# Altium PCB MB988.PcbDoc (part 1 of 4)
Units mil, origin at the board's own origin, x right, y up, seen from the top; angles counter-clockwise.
Board outline 4505 x 6805 mil, 4 copper layers (TopLayer, VCC, GND, BottomLayer), stack 71.6 mil thick; 546 components, 390 nets, 1907 pads, 809 vias.
Unrouted connection lines stored in the file: 2.
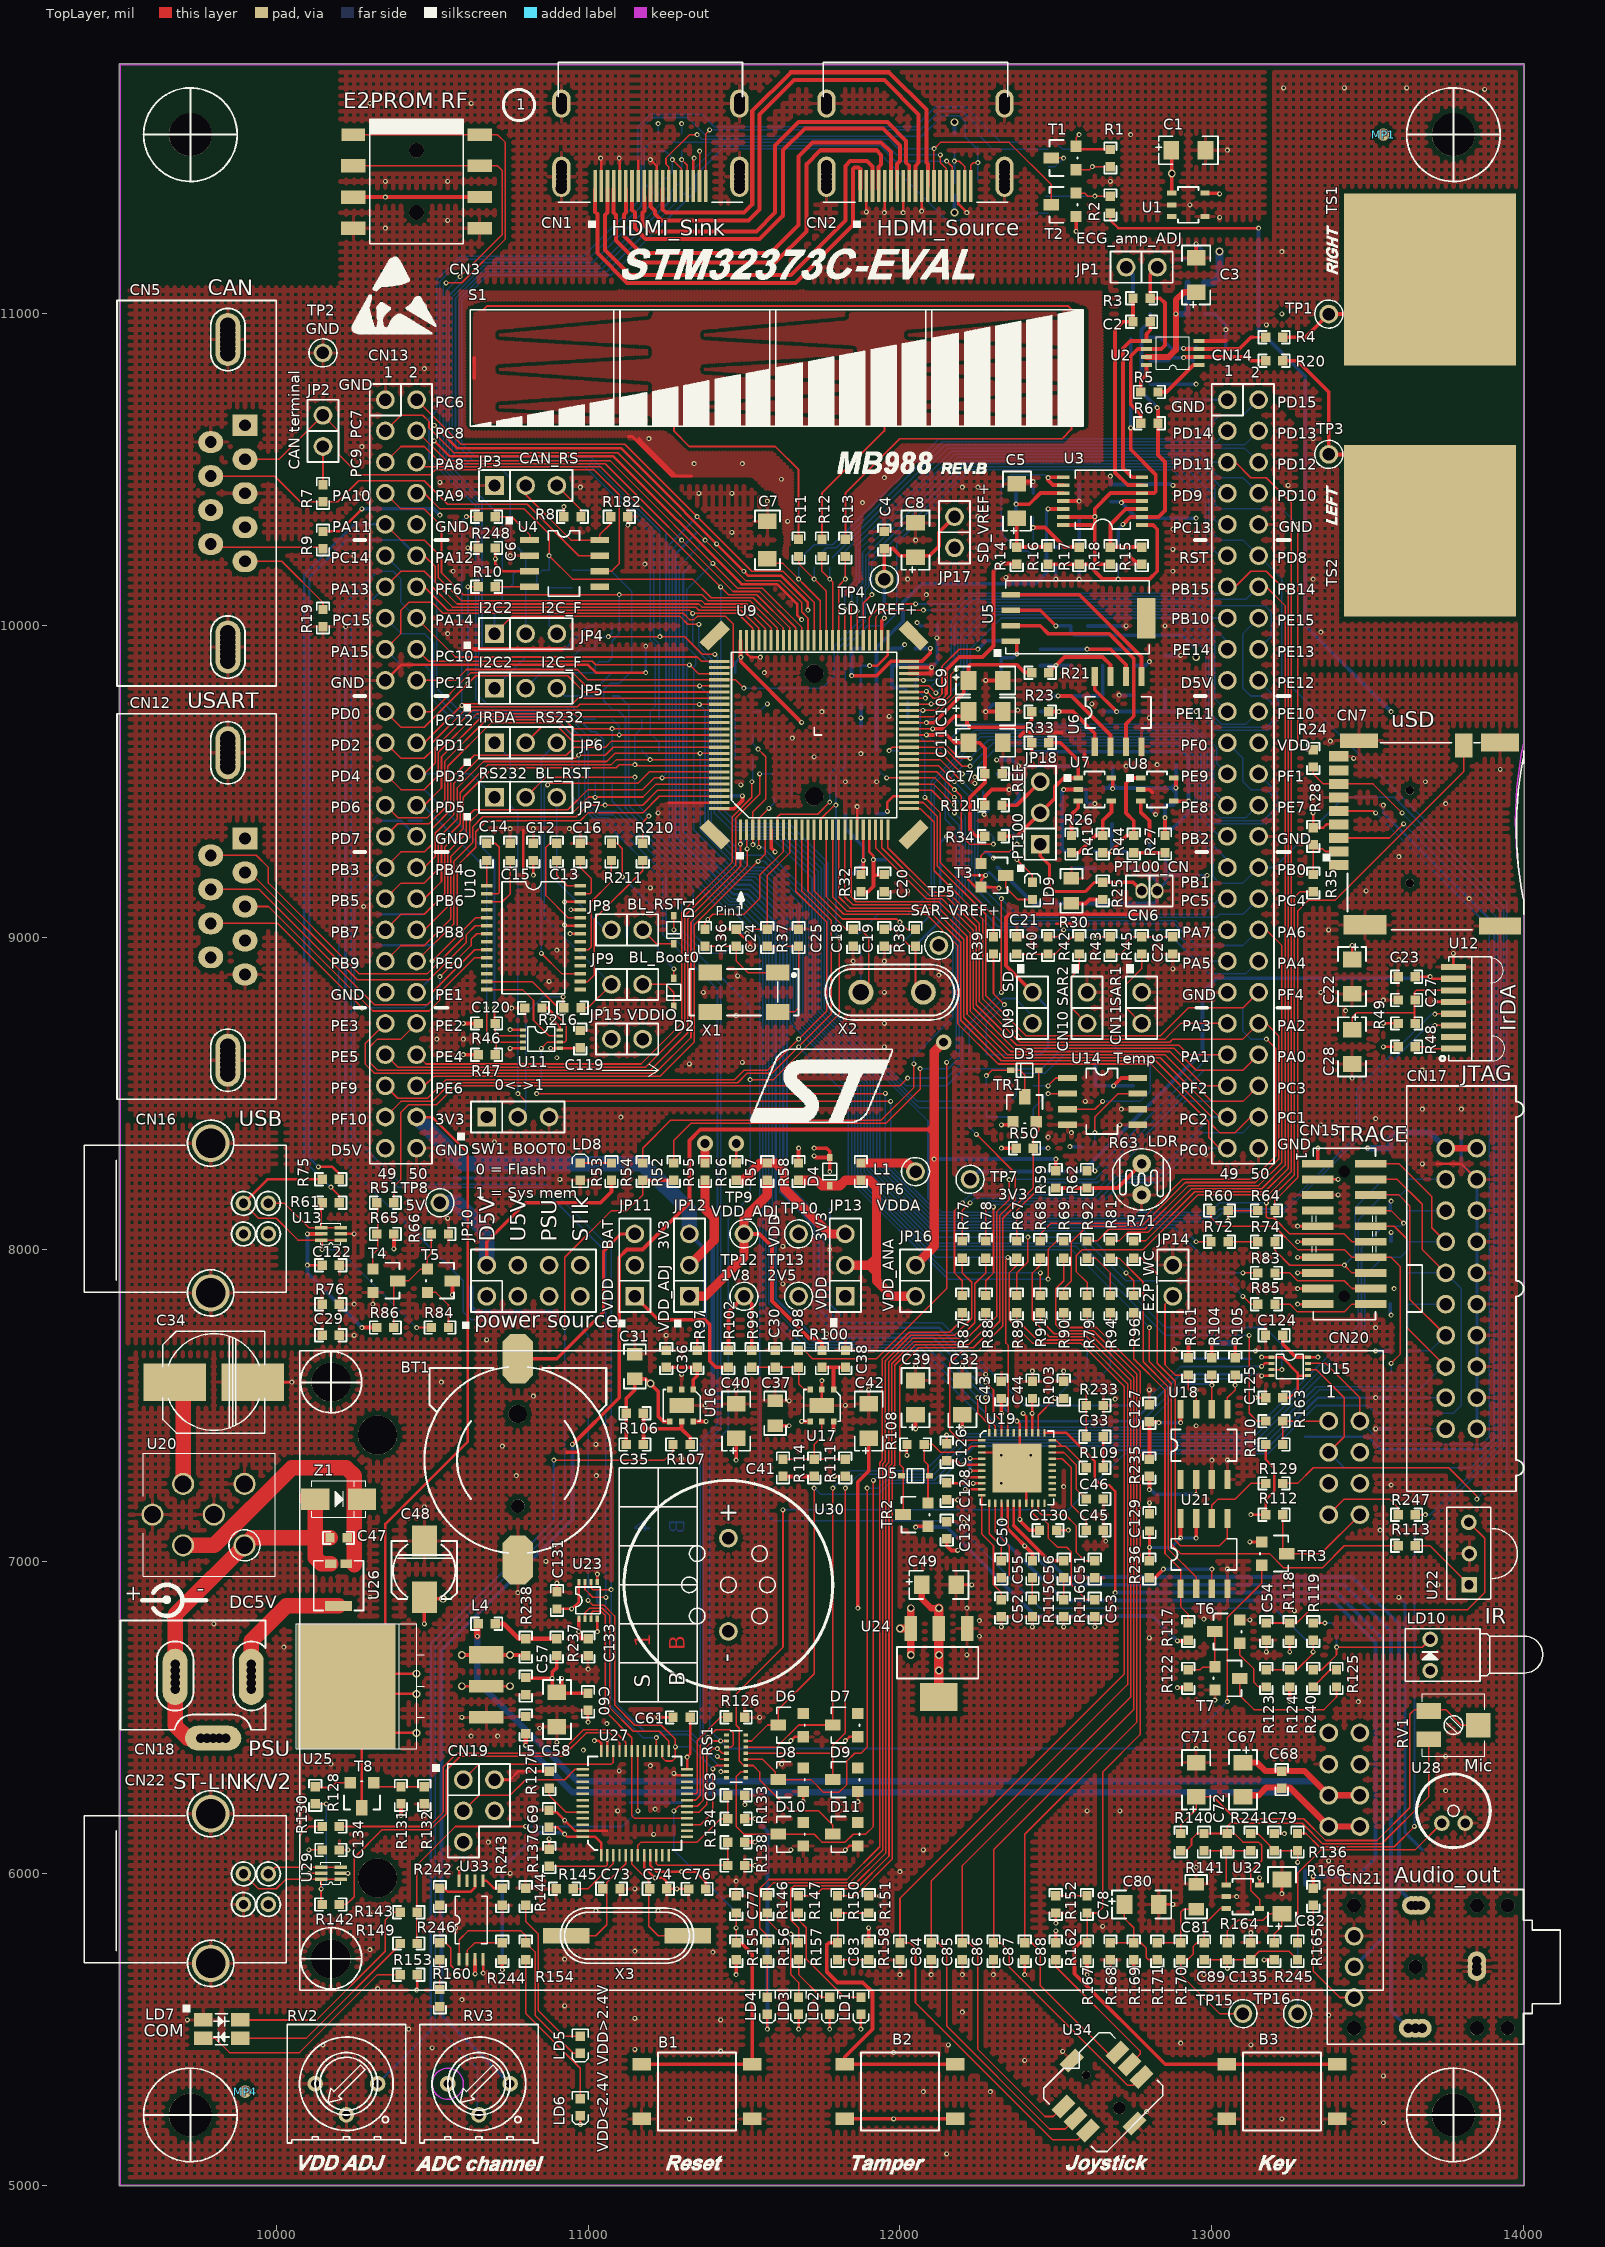
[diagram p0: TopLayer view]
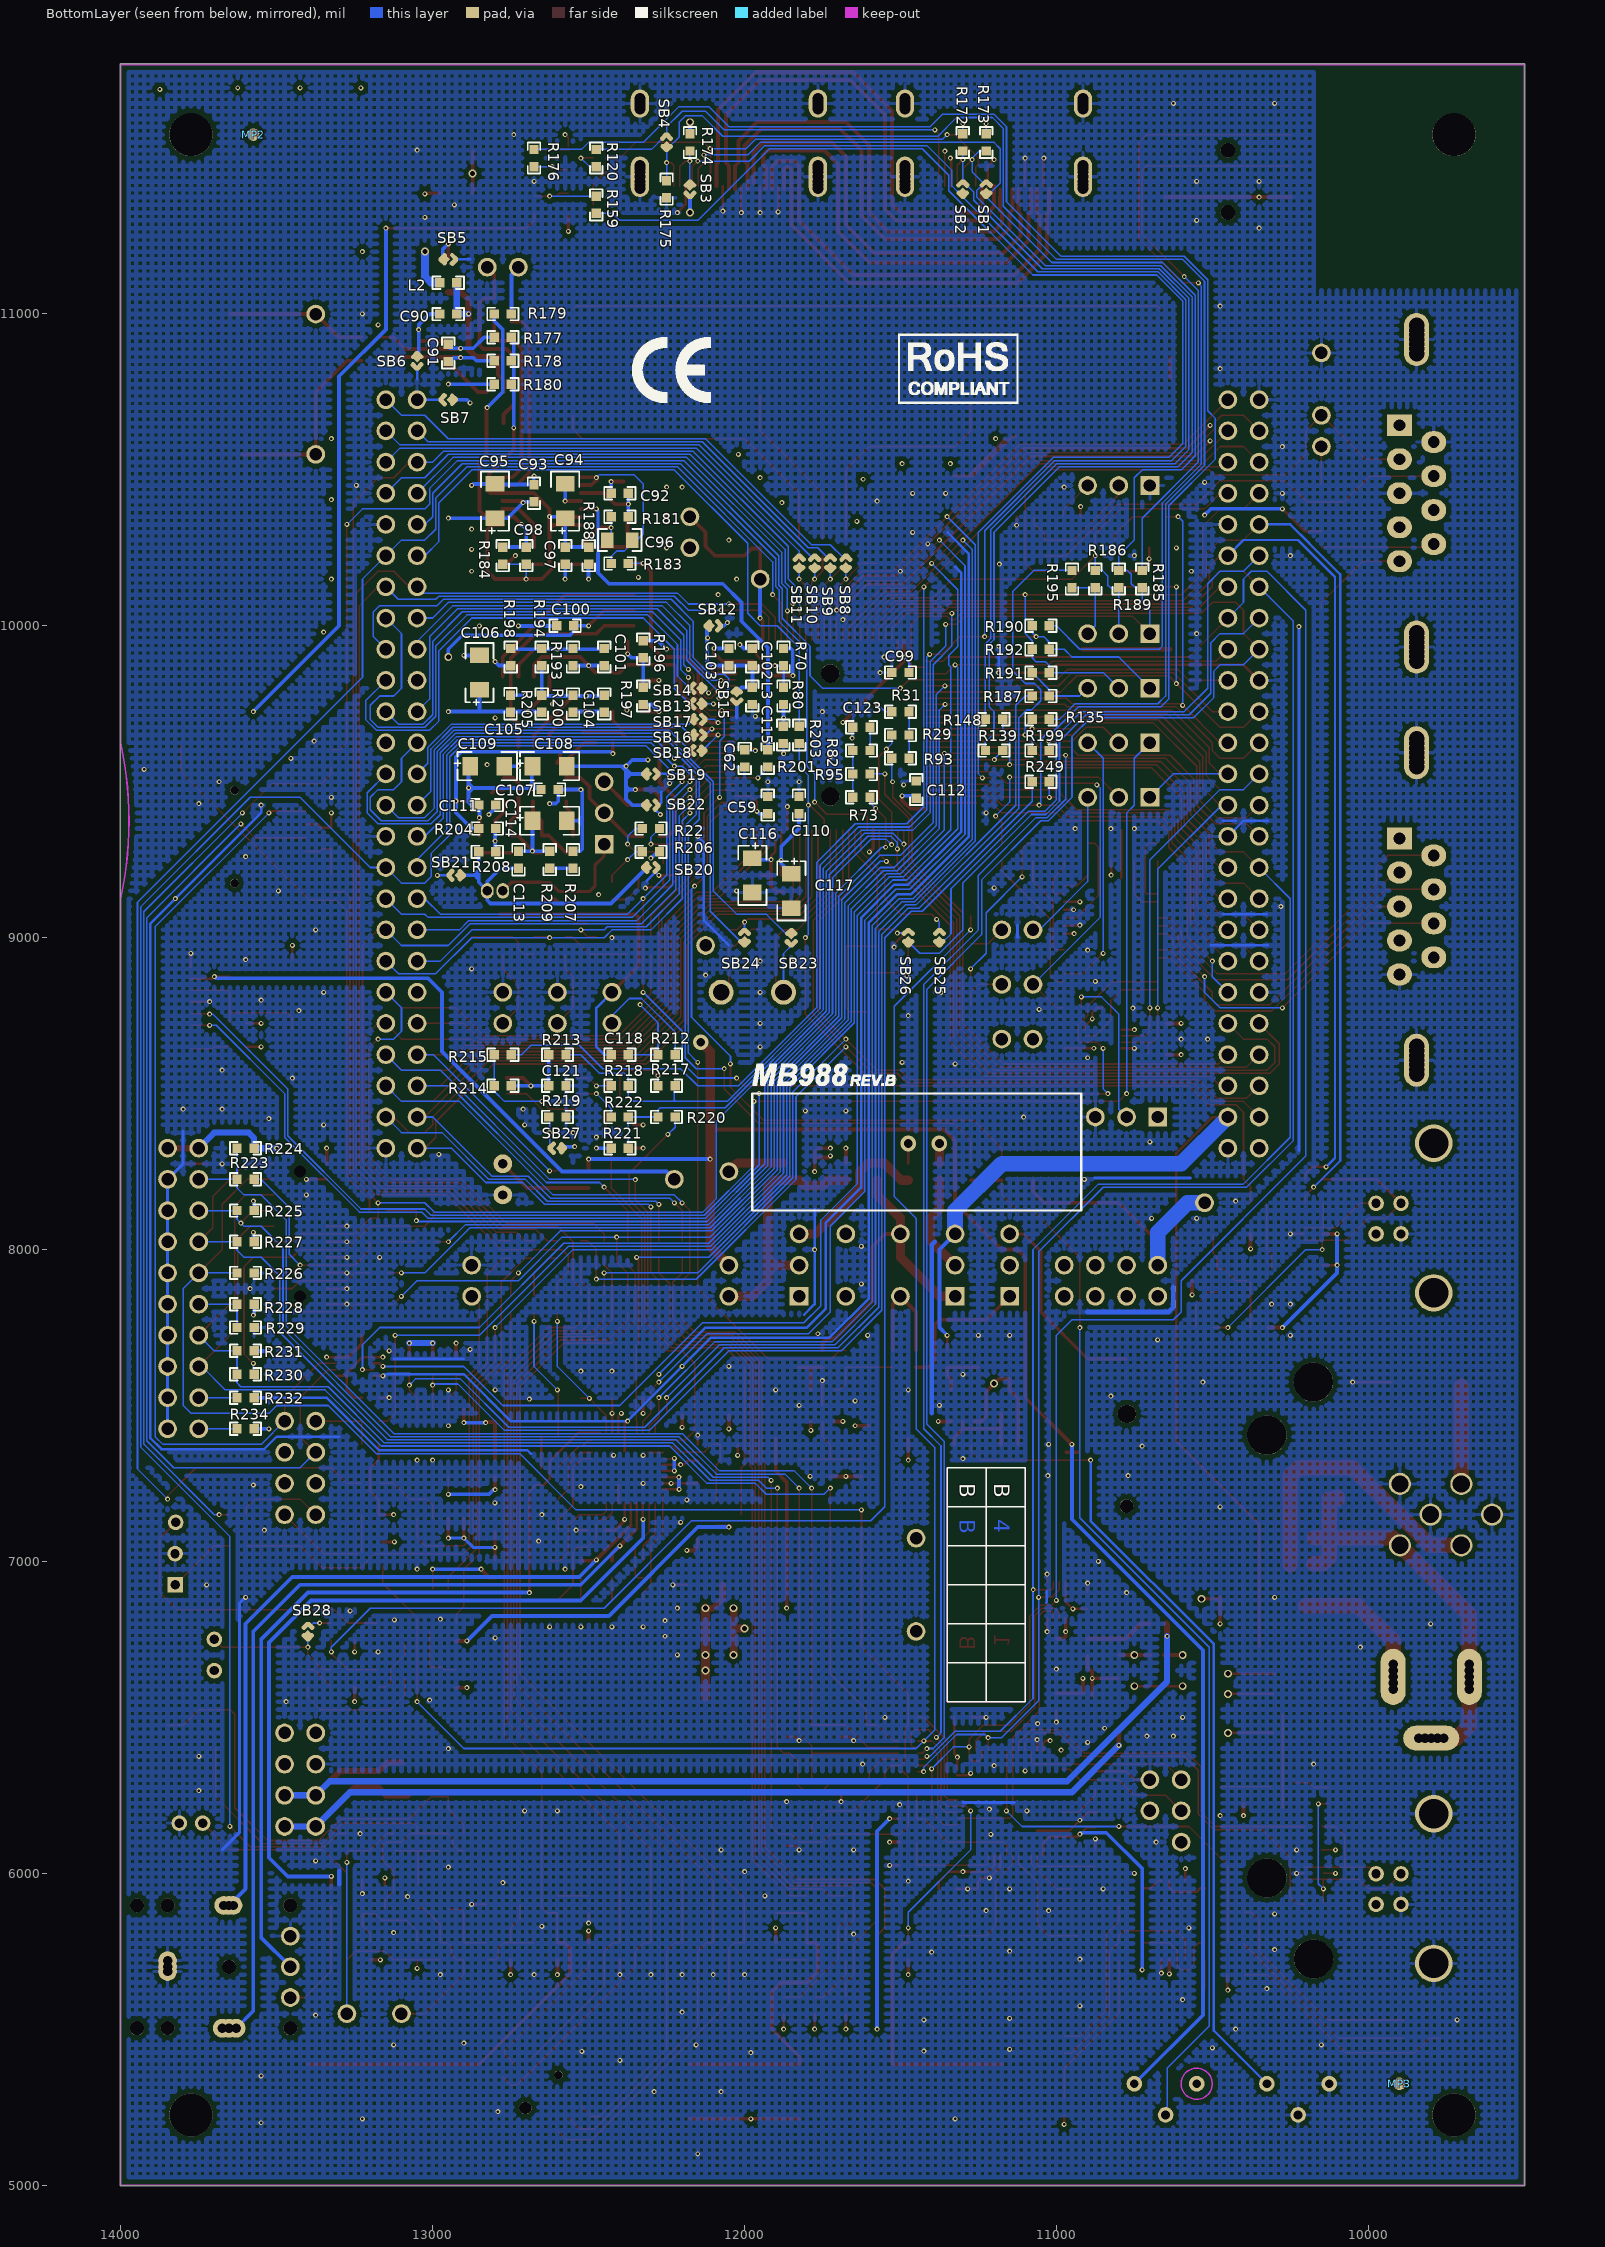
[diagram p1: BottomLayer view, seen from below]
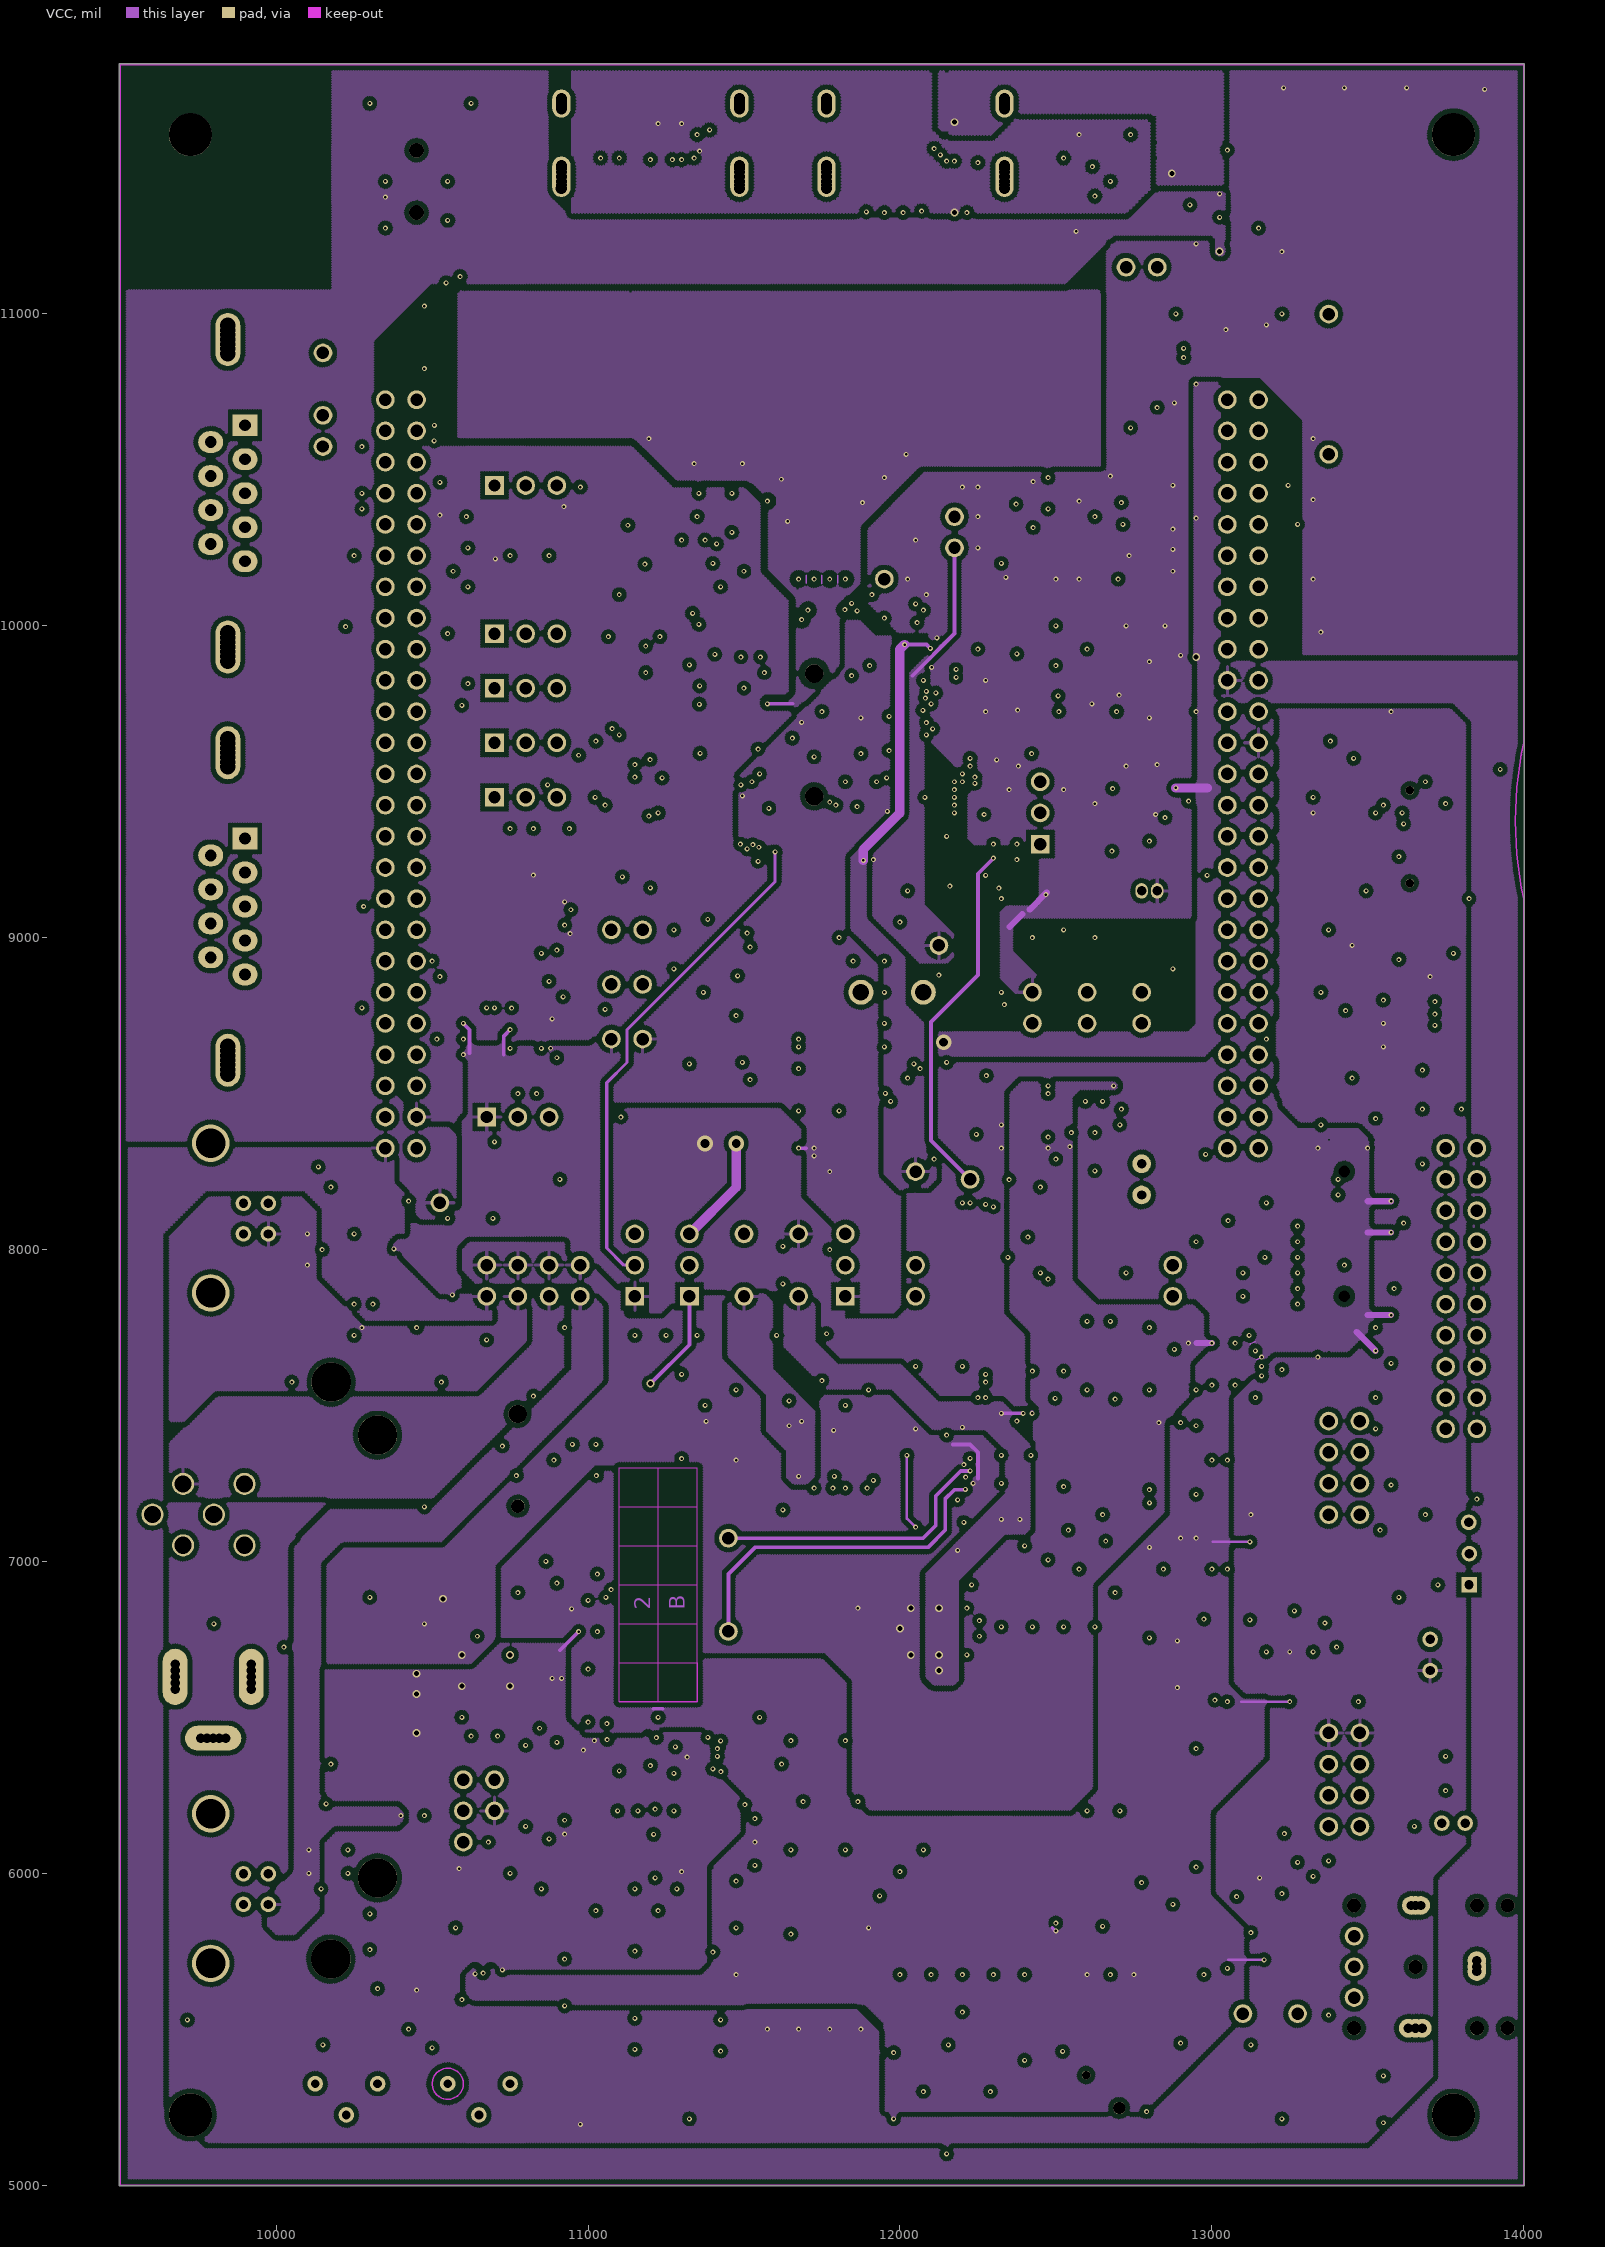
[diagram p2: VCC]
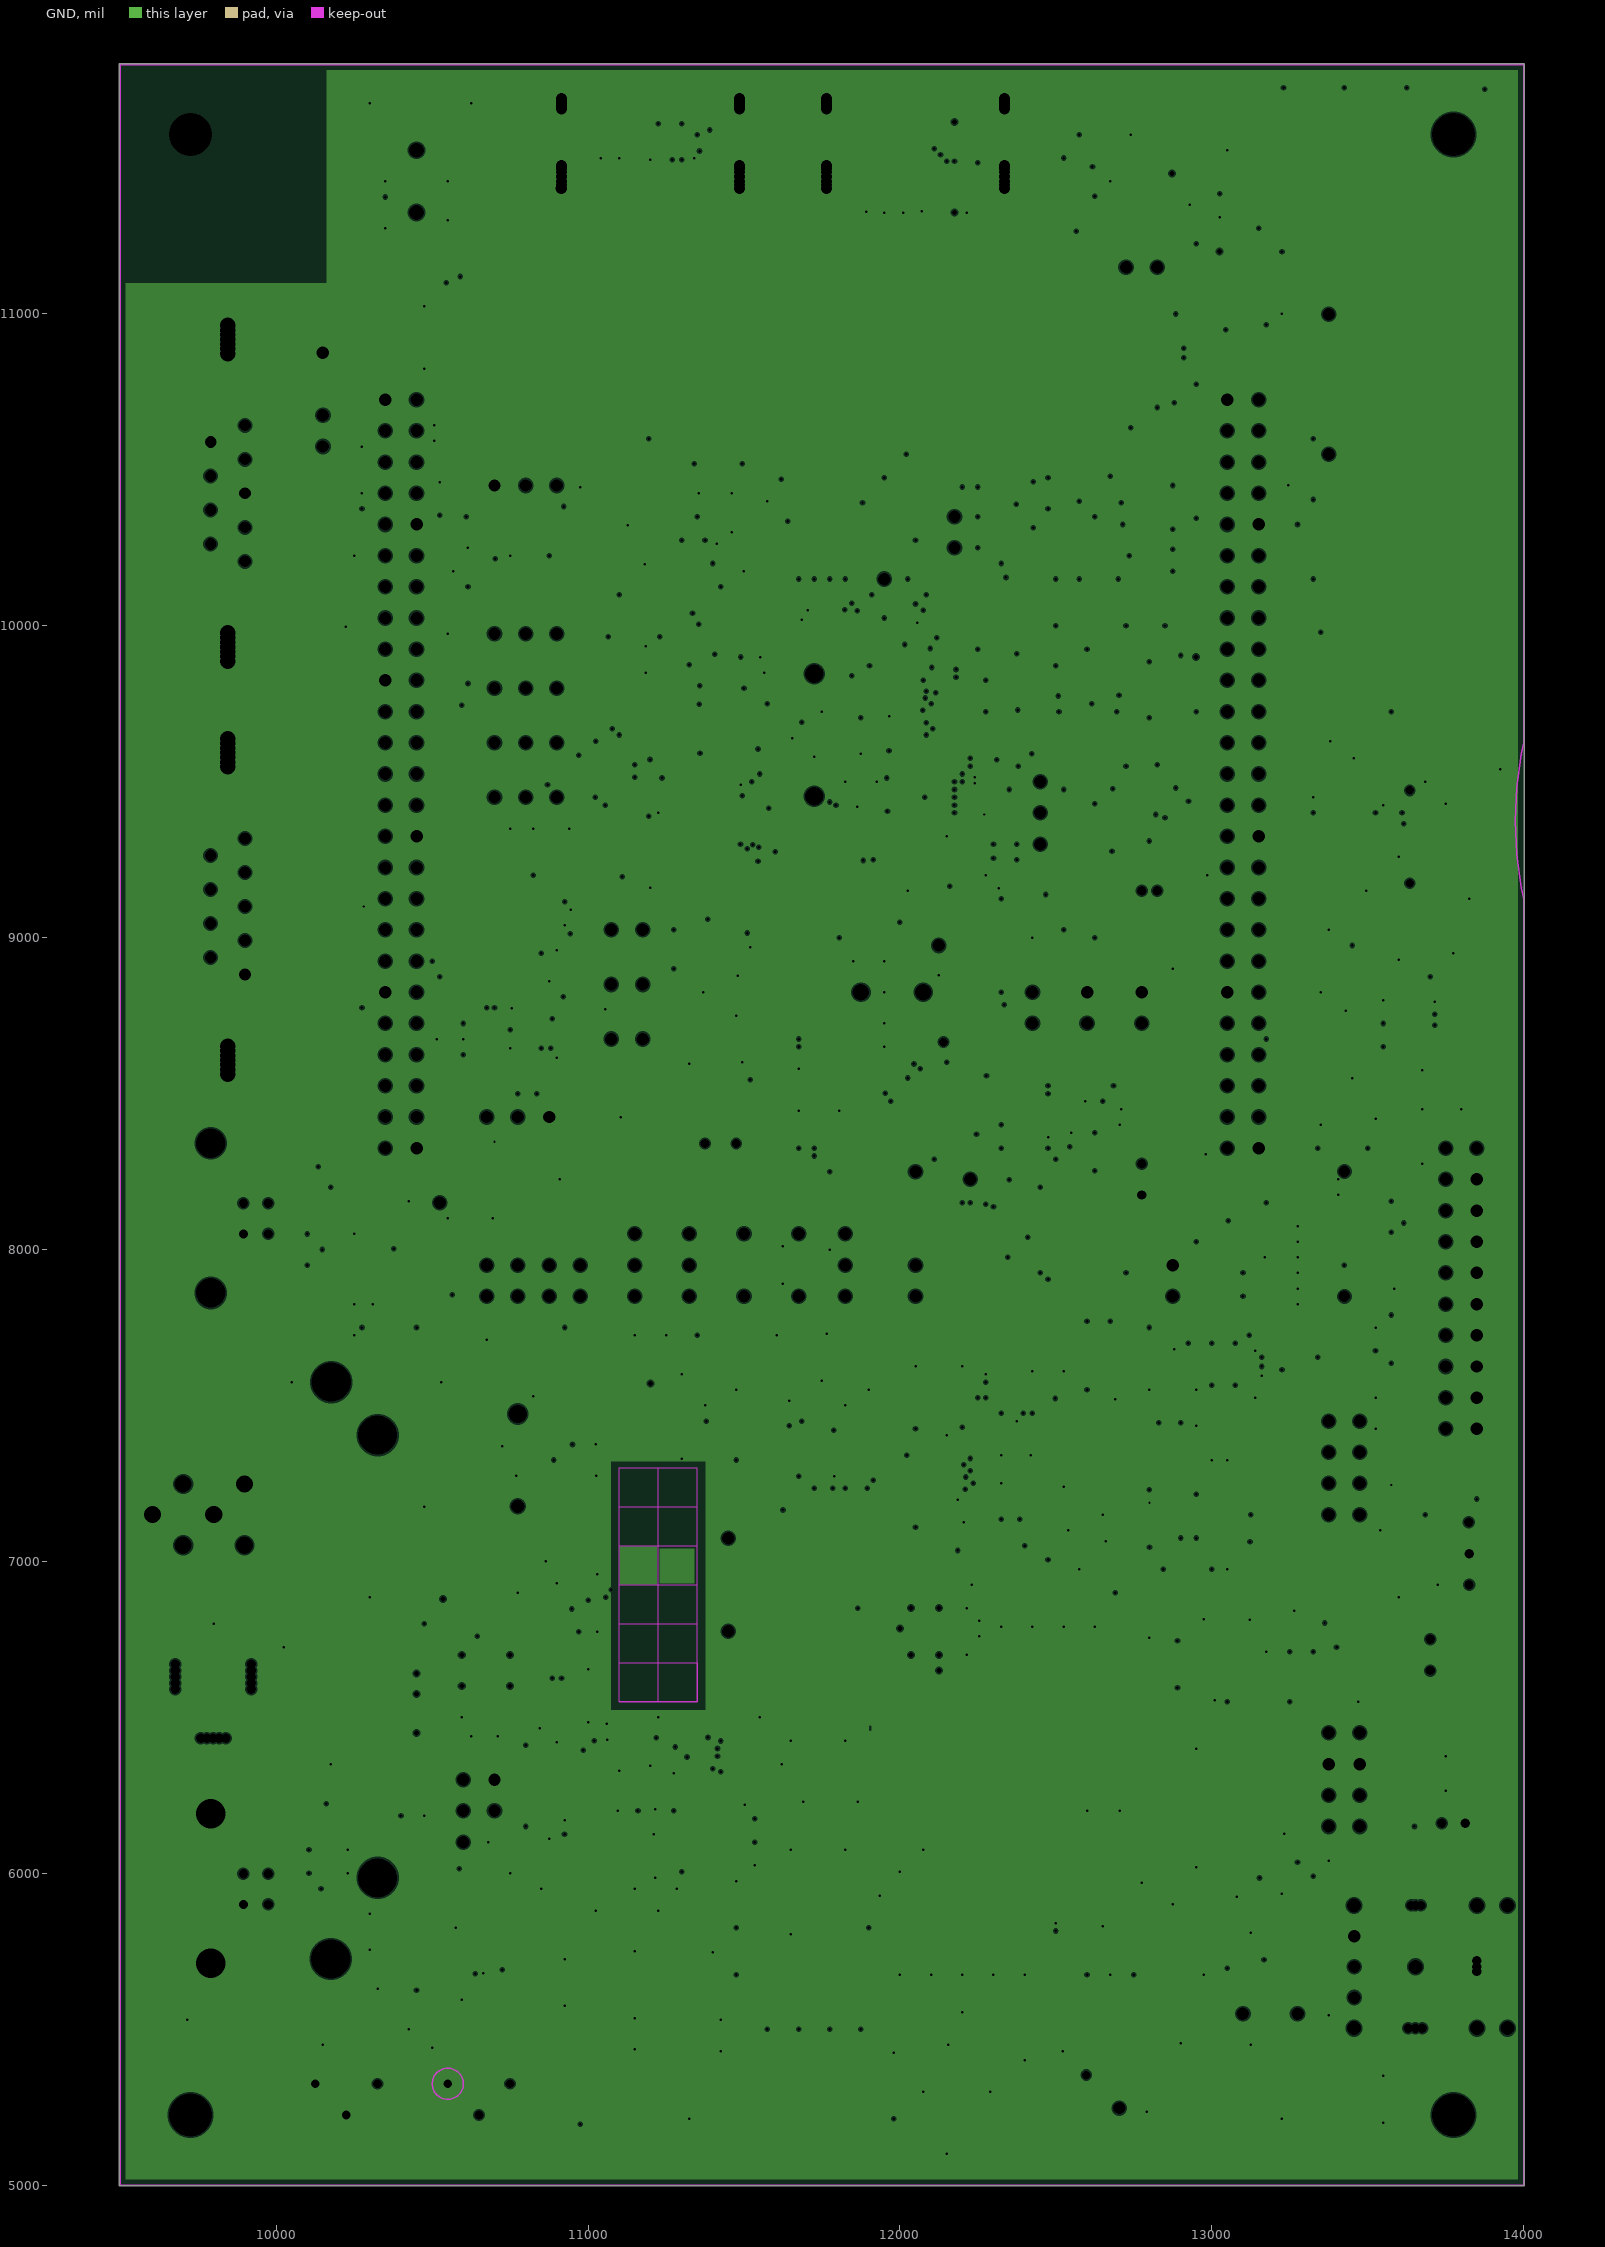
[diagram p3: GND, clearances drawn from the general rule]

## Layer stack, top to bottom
TopLayer: signal copper 0.7
Dielectric: prepreg 4.2, 2116, Dk 4.5
VCC: signal copper 1.4
Dielectric: core 59, FR-4, Dk 4.3
GND: plane copper 1.4, net (Multiple Nets)
Dielectric: prepreg 4.2, 2116, Dk 4.5
BottomLayer: signal copper 0.7

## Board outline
9497.5,4997.5 14002.5,4997.5 14002.5,11802.5 9497.5,11802.5

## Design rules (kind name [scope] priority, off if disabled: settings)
Clearance Clearance_4 [OnLayer('TopLayer') And ((InPoly)) vs InNet('TS_SHIELD')] p1: gap=20
Clearance Clearance_5 [(InPoly) vs InNet('SLD_1')] p2: gap=10
Clearance Clearance_1 [(InPoly) vs InNet('SLD_2')] p3: gap=10
Clearance Clearance_2 [(InPoly) vs InNet('SLD_3')] p4: gap=10
Clearance Clearance_6 [(InPoly)] p5: gap=15
Clearance Clearance_3 [All] p6 off: gap=10
Clearance [All] p7: gap=5
ComponentClearance [All] p1 off: gap=10 collisioncheckmode=3 verticalgap=10
HoleSize [All] p1: absolutevalues=TRUE maxlimit=200 minlimit=1 maxpercent=80.000 minpercent=20.000
PlaneClearance [All] p1: clearance=5
PlaneConnect PlaneConnect_1 [All] p1: planeconnectstyle=Relief reliefexpansion=5 reliefentries=4 reliefconductorwidth=5 reliefairgap=5
PolygonConnect [All] p1: connectstyle=Relief reliefconductorwidth=10 reliefentries=4 polygonreliefangle="90 Angle"
RoutingLayers [All] p1: top layer_v5=FALSE mid layer 1_v5=FALSE bottom layer_v5=FALSE
RoutingVias RoutingVias_1 [All] p1: holewidth=8 width=16 viastyle="Through Hole" minholewidth=8 minwidth=15 maxholewidth=28 maxwidth=50
SolderMaskExpansion [All] p1: expansion=4
TestPointUsage [All] p1: valid=0 allowmultiple=FALSE
Testpoint [All] p1: side=3 testpointundercomponent=TRUE minsize=40 maxsize=100 preferedsize=60 minholesize=20 maxholesize=40 preferedholesize=32 testpointgrid=1 style=297 order=0-112345678
Width Width_4 [InNet('AGND')] p1: maxlimit=300 minlimit=7 preferedwidth=20
Width Width_12 [InNet('VDD')] p2: maxlimit=300 minlimit=5 preferedwidth=10
Width Width_13 [InNet('VDD_ADJ')] p3: maxlimit=300 minlimit=5 preferedwidth=12
Width Width_10 [InNet('SD_VREF+')] p4: maxlimit=300 minlimit=5 preferedwidth=8
Width Width_11 [InNet('U5V')] p5: maxlimit=300 minlimit=5 preferedwidth=8
Width Width_16 [InNet('VDDIO')] p6: maxlimit=300 minlimit=5 preferedwidth=8
Width Width_17 [InNet('+5V')] p7: maxlimit=300 minlimit=5 preferedwidth=20
Width Width_14 [InNet('VDD_ANA')] p8: maxlimit=300 minlimit=5 preferedwidth=12
Width Width_15 [InNet('VDDA')] p9: maxlimit=300 minlimit=5 preferedwidth=12
Width Width_8 [InNet('SAR_VREF+')] p10: maxlimit=300 minlimit=5 preferedwidth=8
Width Width_9 [InNet('GND')] p11: maxlimit=300 minlimit=5 preferedwidth=15
Width Width_7 [InNet('VDD')] p12: maxlimit=300 minlimit=5 preferedwidth=5
Width Width_5 [InNet('E5V')] p13: maxlimit=300 minlimit=5 preferedwidth=50
Width Width_1 [InNet('+1V8')] p14: maxlimit=300 minlimit=5 preferedwidth=12
Width Width_6 [InNet('D5V')] p15: maxlimit=300 minlimit=5 preferedwidth=8
Width Width_3 [InNet('+3V3')] p16: maxlimit=300 minlimit=5 preferedwidth=12
Width Width_2 [InNet('+2V5')] p17: maxlimit=300 minlimit=5 preferedwidth=12
Width [All] p18: maxlimit=300 minlimit=5 preferedwidth=5
14 further rules are at their usual default settings.

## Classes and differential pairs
component class CAN&IR: C6 C54 CN5 JP2 JP3 LD10 R7 R8 R9 R10 R19 R113 R118 R119 R122 R123 R124 R125 R182 R240 R248 R249 SB28 T6 T7 U4 U22
component class MB964: MP1 MP4
component class MCU: BT1 C30 C31 C35 C37 C39 C42 C47 C55 C56 C58 C64 C80 C82 C83 C85 C87 C103 C132 CN13 JP2 JP5 JP8 JP11 JP14 JP15 JP18 JP19 JP21 JP22 LD7 PB1 PB2 R6 R10 R11 R13 R20 R31 R35 R51 R55 R56 R69 R70 R71 R74 R77 R79 R85 R91 R97 R98 R99 R111 R114 R116 R118 R119 R121 R124 R127 R130 R132 R133 R134 R152 R153 R155 R159 R163 R177 R178 R182 R202 R225 R228 R239 R246 TP2 U14 U33 X1 X3
component class Peripherals: C9 C32 C36 C40 C51 C102 CN1 CN3 CN15 JP3 JP7 JP9 JP12 R60 R61 R64 R83 R90 R144 R166 R217 R223 R225 R226 T7 U13 U17 U24 U31
component class Audio: C25 C35 C41 C66 C69 C81 C99 C116 C128 JP13 JP26 R17 R37 R57 R92 R132 R151 R156 R231 R232 R241 TP7 TP8 TP9 TP12 TP13 TP15 U9 U24 U25
component class Ethernet: C4 C18 C20 C35 C44 C49 C65 C73 C74 C102 C115 CN23 JP24 JP25 L1 L4 R8 R10 R11 R16 R19 R55 R57 R66 R68 R80 R82 R84 R93 R99 R119 R120 R125 R134 R135 R138 R142 R184 TP4 U22 X3
component class JTAG&ETM: C4 CN5 CN19 JP20 R9 R61 R87 R89 R96 R102 R140 R146 R150 R216 R229 R236
component class UART&IrDA: C8 C47 C49 C51 C54 C61 C62 C69 C71 C76 C112 C116 CN2 CN5 JP1 JP4 JP23 R9 R73 R202 R224 R242 U20 U28 U30
component class Power: C19 C34 C35 C46 C49 C52 C53 C65 C77 C85 C89 C96 C126 C133 CN22 JP1 L5 LD7 R31 TP6 TP15 TP16 U2 U20 U22 Z1
component class LCD&Joystick: C19 C58 C103 R8 R12 R15 R18 R23 R53 R65 R67 R76 R93 R106 R117 R123 R135 R171 R176 R177 R178 R180 R236 R243 U23 U25 U26 U34
component class IDD_measurement: C46 C58 C102 JP2 R83 R88 R184 R216 R217 R242 T6 T8 U17 U20 U31 U33
component class SRAM&Flash: C18 C29 C35 C43 C50 C81 C87 C122 JP11 R13 R71 R76 R91 R96 R117 R158 R165 R236 R243 U9 U25
component class TouchSlider: C51 C53 R85 R202 R225 R226 R228 S1 SB9 SB10 SB11 SB28
component class LCD_RS232_IrDA: C19 C25 C31 C34 C40 C44 C60 C65 C69 C77 C89 C91 C93 C127 C131 CN19 CN22 JP6 JP13 JP17 L1 L4 R6 R9 R51 R61 R75 R80 R96 R119 R128 R140 R152 R153 R244 U20 U22 U23 U30
component class ST_LINK: C4 C57 C58 C61 C73 C74 C76 C110 C117 CN5 CN23 LD7 R8 R10 R11 R12 R31 R70 R118 R121 R125 R132 R133 R142 R239 R246 T7 U17 U26 X3
component class TemSensor&RF_E2PROM&SPI_FLASH: C53 C84 CN18 R10 R31 R37 R56 R57 R74 R77 R82 R92 R135 R138 R169 R177 R202 R226 R228 SB4 TR1 TR2 U5 U34
component class Extensionconnector: CN19 CN21 R89 R159 R234 SB1 SB4 SB8 SB24
component class JTAG&Trace: CN2 CN19 R35 R56 R61 R70 R76 R77 R111 R124 R163 R182 R229 R236 R239 RS1
component class MicroSD: CN13 R60 R144 R150 R151 R156 R231
net class PA[0..15]: PA0 PA1 PA2 PA3 PA4 PA5 PA7 PA8 PA9 PA10 PA11 PA12 PA13 PA14 PA[0..15]0 PA[0..15]1 PA[0..15]2 PA[0..15]3 PA[0..15]4 PA[0..15]5 PA[0..15]6 PA[0..15]7 PA[0..15]8 PA[0..15]9 PA[0..15]10 PA[0..15]11 PA[0..15]12 PA[0..15]13 PA[0..15]14 PA[0..15]15 T_JTDI "TMDS DATA0+"
net class PB[0..15]: NetR118_2 NetR139_1 NetR148_1 PB0 PB1 PB2 PB3 PB5 PB8 PB10 PB11 PB12 PB13 PB14 PB15 PB[0..15]0 PB[0..15]1 PB[0..15]2 PB[0..15]3 PB[0..15]4 PB[0..15]5 PB[0..15]6 PB[0..15]7 PB[0..15]8 PB[0..15]9 PB[0..15]10 PB[0..15]11 PB[0..15]12 PB[0..15]13 PB[0..15]14 PB[0..15]15 T_JRST
net class PC[0..15]: NetC83_2 NetSB24_2 PC0 PC1 PC2 PC3 PC4 PC6 PC7 PC8 PC9 PC10 PC11 PC12 PC14 PC15 PC[0..15]0 PC[0..15]1 PC[0..15]2 PC[0..15]3 PC[0..15]4 PC[0..15]5 PC[0..15]6 PC[0..15]7 PC[0..15]8 PC[0..15]9 PC[0..15]10 PC[0..15]11 PC[0..15]12 PC[0..15]13 PC[0..15]14 PC[0..15]15
net class PD[0..15]: NetSB4_2 PD0 PD1 PD2 PD3 PD4 PD5 PD6 PD8 PD9 PD10 PD11 PD12 PD13 PD14 PD15 PD[0..15]0 PD[0..15]1 PD[0..15]2 PD[0..15]3 PD[0..15]4 PD[0..15]5 PD[0..15]6 PD[0..15]7 PD[0..15]8 PD[0..15]9 PD[0..15]10 PD[0..15]11 PD[0..15]12 PD[0..15]13 PD[0..15]14 PD[0..15]15
net class PE[0..15]: PE0 PE1 PE2 PE3 PE4 PE5 PE6 PE7 PE8 PE9 PE10 PE11 PE12 PE13 PE14 PE15 PE[0..15]0 PE[0..15]1 PE[0..15]2 PE[0..15]3 PE[0..15]4 PE[0..15]5 PE[0..15]6 PE[0..15]7 PE[0..15]8 PE[0..15]9 PE[0..15]10 PE[0..15]11 PE[0..15]12 PE[0..15]13 PE[0..15]14 PE[0..15]15
net class PH[0..2]: PH0 PH1 PH2 PH[0..2]0 PH[0..2]1 PH[0..2]2
net class PF[0..15]: PF0 PF1 PF2 PF3 PF4 PF5 PF6 PF7 PF8 PF9 PF10 PF11 PF12 PF13 PF14 PF15 PF[0..15]0 PF[0..15]1 PF[0..15]2 PF[0..15]3 PF[0..15]4 PF[0..15]5 PF[0..15]6 PF[0..15]7 PF[0..15]8 PF[0..15]9 PF[0..15]10 PF[0..15]11 PF[0..15]12 PF[0..15]13 PF[0..15]14 PF[0..15]15
net class PG[0..15]: PG0 PG1 PG2 PG3 PG4 PG5 PG6 PG7 PG8 PG9 PG10 PG11 PG12 PG13 PG14 PG15 PG[0..15]0 PG[0..15]1 PG[0..15]2 PG[0..15]3 PG[0..15]4 PG[0..15]5 PG[0..15]6 PG[0..15]7 PG[0..15]8 PG[0..15]9 PG[0..15]10 PG[0..15]11 PG[0..15]12 PG[0..15]13 PG[0..15]14 PG[0..15]15
net class D[0..15]: D0 D1 D2 D3 D4 D5 D6 D7 D8 D9 D10 D11 D12 D13 D14 D15 D[0..15]0 D[0..15]1 D[0..15]2 D[0..15]3 D[0..15]4 D[0..15]5 D[0..15]6 D[0..15]7 D[0..15]8 D[0..15]9 D[0..15]10 D[0..15]11 D[0..15]12 D[0..15]13 D[0..15]14 D[0..15]15
net class A[0..23]: A0 A1 A2 A3 A4 A5 A6 A7 A8 A9 A10 A11 A12 A13 A14 A15 A16 A17 A18 A19 A20 A21 A22 A23 A[0..23]0 A[0..23]1 A[0..23]2 A[0..23]3 A[0..23]4 A[0..23]5 A[0..23]6 A[0..23]7 A[0..23]8 A[0..23]9 A[0..23]10 A[0..23]11 A[0..23]12 A[0..23]13 A[0..23]14 A[0..23]15 A[0..23]16 A[0..23]17 A[0..23]18 A[0..23]19 A[0..23]20 A[0..23]21 A[0..23]22 A[0..23]23
component class MB694: MP1 MP4
component class HDMI_CEC: C45 CN13 CN17 R60 R144 R150 R151 R156 R158 R165 R231 R232 R234 SB8 SB9 SB10 SB24 T6 T8 U9
component class LCD_MicroSD: C6 C75 CN1 CN3 L1 L4 R7 R13 R51 R71 R75 R126 R143 R148 R153 R162 TR1
component class MB965: C8 C34 C38 C86 C87 C88 R36 R38 R69 R81 R83 R90 R91 R95 R96 R117 R140 R141 R147 R155 R171 R223 R227 R242 R243 U13 U16 U21
component class MotorCtrl: C19 C24 C25 C32 C33 C43 C46 C50 C52 C81 C126 C130 C132 CN21 JP1 JP9 R29 R64 R72 R73 R79 R94 R103 R109 R179 R220 SB25 SB26
component class RS232_RS485_IrDA: C39 C55 C56 C72 C79 C80 C82 C83 C128 C135 CN18 JP8 R35 R87 R115 R116 R157 R246 SB2 SB3 SB11 U19 U28 U33
component class ST_LINK_V2: C4 C57 C58 C61 C73 C74 C76 C110 C117 CN5 CN23 LD7 R8 R10 R11 R12 R31 R70 R118 R121 R122 R124 R125 R132 R133 R182 R239 T7 U17 U26 X3
component class TemSensor_RF_EEPROM: C84 CN15 R77 R167 U34
component class JTAG&SWD: CN19 D6 D7 D9 JP17 R56 R61 R76 R111 R127 R128 R137 R163 R236
component class CAN&SmartCard&IR: C6 C54 C59 C62 C64 C65 C66 C70 C75 CN5 CN23 JP2 JP3 LD8 R7 R8 R9 R10 R19 R70 R80 R93 R95 R113 R118 R119 R120 R121 R122 R123 R124 R125 R129 R135 R139 R182 R239 R240 SB28 T6 T7 TP11 TP14 U4 U22 U31
component class ECG&PressureSensor: C2 C3 C5 C9 C10 C90 C91 C92 C93 C94 C96 C97 C98 C100 C101 C104 C105 JP1 L2 R3 R4 R5 R6 R14 R15 R16 R17 R18 R20 R21 R23 R177 R178 R179 R180 R181 R183 R184 R188 R193 R194 R196 R197 R198 R200 R205 TP1 TP3 TS1 TS2 U2 U3 U5 U6
component class I2CPeripherals: C121 C127 CN3 JP14 R101 R104 R105 R185 R187 R190 R195 R214 R215 R218 R219 R222 R235 SB27 U14 U18
component class RS232_IrDA: C12 C13 C14 C15 C16 C22 C23 C27 C28 C119 C120 CN12 CN19 JP6 JP7 R46 R47 R48 R49 R199 R203 R206 R209 R210 R211 U10 U11 U12 U37
component class TemSensor&CON: C11 C17 C21 C26 C107 C111 C113 C114 C118 CN6 CN9 CN10 CN11 R25 R26 R27 R30 R33 R34 R39 R40 R41 R42 R43 R44 R45 R52 R54 R59 R62 R63 R204 R207 R208 R209 R212 RV3 U7 U8
component class MB988: JP4 JP5 MP1 MP4 R186 R189 R191 R192

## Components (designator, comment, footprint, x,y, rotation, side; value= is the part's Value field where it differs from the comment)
B1 "TD-0341 [RESET/Black]" PB10 11349,5300 r0 top
B2 "WKUP" PB10 12000,5300 r0 top
B3 "USER (Blue)" PB10 13225,5300 r0 top
BT1 "CR1220 holder" LI1220_1 10775,7325 r90 top
C1 "4.7uF" TAN-A 12925,11525 r180 top
C2 "100nF" 0603C#1 12775,10975 r0 top
C3 "4.7uF" TAN-A 12950,11125 r270 top
C4 "100nF" 0603C#1 11950,10275 r90 top
C5 "10uF" TAN-A 12375,10400 r270 top
C6 "100nF" 0603C#1 10675,10250 r180 top
C7 "47nF(COG)GRM31M5C1H473JA01L" 1206C 11575,10275 r90 top
C8 "1uF" TAN-A 12050,10275 r270 top
C9 "10uF" TAN-A 12275,9825 r180 top
C10 "10uF" TAN-A 12275,9725 r180 top
C11 "10uF" TAN-A 12275,9625 r180 top
C12 "100nF" 0603C#1 10825,9275 r90 top
C13 "100nF" 0603C#1 10900,9275 r90 top
C14 "100nF" 0603C#1 10675,9275 r270 top
C15 "100nF" 0603C#1 10750,9275 r270 top
C16 "100nF" 0603C#1 10975,9275 r270 top
C17 "100nF" 0603C#1 12300,9525 r0 top
C18 "20pF" 0603C#2 11850,9000 r90 top
C19 "20pF" 0603C#2 11950,9000 r90 top
C20 "100nF" 0603C#1 11950,9175 r270 top
C21 "[N/A]" 0603C#2 12375,8975 r90 top
C22 "4.7uF" TAN-A 13450,8875 r90 top
C23 "100nF" 0603C#1 13625,8875 r0 top
C24 "6.8pF" 0603C#2 11475,9000 r270 top
C25 "6.8pF" 0603C#2 11675,9000 r270 top
C26 "[N/A]" 0603C#2 12875,8975 r270 top
C27 "100nF" 0603C#1 13625,8800 r0 top
C28 "4.7uF" TAN-A 13450,8650 r90 top
C29 "4.7nF" 0603C#2 10175,7725 r0 top
C30 "100nF" 0603C#1 11600,7650 r270 top
C31 "10uF" 0805C#1 11150,7625 r270 top
C32 "1uF" TAN-A 12200,7525 r270 top
C33 "1uF" 0603C#2 12625,7400 r0 top
C34 "220uF" C310M 9800,7575 r180 top
C35 "[N/A]" 0603C#2 11150,7375 r0 top
C36 "100nF" 0603C#1 11250,7650 r270 top
C37 "10uF" 0805C#1 11600,7475 r270 top
C38 "[N/A]" 0603C#1 11825,7650 r270 top
C39 "10uF" TAN-A 12050,7525 r270 top
C40 "4.7uF" TAN-A 11475,7450 r270 top
C41 "[N/A]" 0603C#2 11625,7300 r90 top
C42 "4.7uF" TAN-A 11900,7450 r270 top
C43 "100nF" 0603C#1 12325,7550 r270 top
C44 "100nF" 0603C#1 12425,7550 r270 top
C45 "150pF(COG)" 0603C#2 12625,7100 r0 top
C46 "150pF(COG)" 0603C#2 12625,7200 r0 top
C47 "100nF" 0603C#1 10200,7075 r0 top
C48 "47uF" C200M 10475,6975 r270 top
C49 "10uF" TAN-A 12125,6925 r180 top
C50 "1uF" 0603C#2 12325,6975 r270 top
C51 "1uF" 0603C#2 12625,6975 r270 top
C52 "1uF" 0603C#2 12325,6850 r90 top
C53 "1uF" 0603C#2 12625,6850 r270 top
C54 "4.7uF" 0603C#2 13175,6775 r90 top
C55 "0.022uF" 0603C#2 12425,6975 r270 top
C56 "0.022uF" 0603C#2 12525,6975 r270 top
C57 "100nF" 0603C#1 10800,6600 r90 top
C58 "10uF" TAN-A 10900,6525 r90 top
C59 "100nF" 0603C#3 11925,9425 r270 bottom
C60 "100nF" 0603C#1 11000,6550 r90 top
C61 "100nF" 0603C#1 11300,6500 r180 top
C62 "100nF" 0603C#1 12000,9575 r270 bottom
C63 "100nF" 0603C#1 11475,6250 r0 top
C67 "10uF" TAN-A 13100,6300 r90 top
C68 "100nF" 0603C#1 13225,6300 r90 top
C69 "100nF" 0603C#1 10875,6175 r90 top
C71 "4.7uF" TAN-A 12950,6300 r270 top
C72 "180pF" 0603C#2 13050,6100 r90 top
C73 "Cap" 0603R#1 11075,5950 r0 top
C74 "Cap" 0603R#1 11225,5950 r0 top
C76 "100nF" 0603C#1 11350,5950 r180 top
C77 "100nF" 0603C#1 11475,5900 r90 top
C78 "100nF" 0603C#1 12600,5900 r90 top
C79 "[N/A]" 0603C#2 13200,6100 r270 top
C80 "4.7uF" TAN-A 12775,5900 r180 top
C81 "2.2uF" 0805C#1 12950,5925 r270 top
C82 "10uF" TAN-A 13225,5925 r270 top
C83 "[N/A]" 0603C#2 11800,5750 r270 top
C84 "10nF" 0603C#1 12000,5750 r270 top
C85 "10nF" 0603C#1 12100,5750 r270 top
C86 "10nF" 0603C#1 12200,5750 r270 top
C87 "10nF" 0603C#1 12300,5750 r270 top
C88 "10nF" 0603C#1 12400,5750 r270 top
C89 "100nF" 0603C#1 12975,5750 r270 top
C90 "100nF" 0603C#1 12950,11000 r0 bottom
C91 "47nF" 0603C#3 12950,10875 r90 bottom
C92 "1uF" 0603C#2 12400,10425 r0 bottom
C93 "100nF" 0603C#1 12675,10425 r90 bottom
C94 "4.7uF" TAN-A 12575,10400 r270 bottom
C95 "1uF" TAN-A 12800,10400 r270 bottom
C96 "10uF" 0805C#2 12400,10275 r0 bottom
C97 "100nF" 0603C#1 12575,10225 r270 bottom
C98 "15nF" 0603C#2 12700,10225 r270 bottom
C99 "100nF" 0603C#1 11500,9850 r180 bottom
C100 "100nF" 0603C#1 12575,10000 r0 bottom
C101 "1uF" 0603C#2 12450,9900 r90 bottom
C102 "100nF" 0603C#1 11975,9900 r270 bottom
C103 "100nF" 0603C#1 12050,9900 r270 bottom
C104 "1uF" 0603C#2 12450,9750 r90 bottom
C105 "100nF" 0603C#1 12750,9750 r90 bottom
C106 "1uF" TAN-A 12850,9850 r270 bottom
C107 "100nF" 0603C#1 12625,9475 r180 bottom
C108 "1uF" TAN-A 12625,9550 r0 bottom
C109 "1uF" TAN-A 12825,9550 r0 bottom
C110 "100nF" 0603C#1 11825,9425 r90 bottom
C111 "100nF" 0603C#1 12825,9425 r180 bottom
C112 "100nF" 0603C#1 11450,9475 r270 bottom
C113 "100nF" 0603C#1 12725,9250 r270 bottom
C114 "10uF" TAN-A 12625,9375 r0 bottom
C115 "100nF" 0603C#1 11875,9650 r90 bottom
C116 "1uF" TAN-A 11975,9200 r90 bottom
C117 "1uF" TAN-A 11850,9150 r90 bottom
C118 "[N/A]" 0603C#2 12400,8625 r0 bottom
C119 "100nF" 0603C#1 10975,8675 r90 top
C120 "100nF" 0603C#1 10825,8775 r180 top
C121 "100nF" 0603C#1 12600,8525 r180 bottom
C122 "100nF" 0603C#1 10175,7950 r180 top
C123 "220nF" 0603C#2 11625,9675 r0 bottom
C124 "100nF" 0603C#1 13200,7725 r180 top
C125 "100nF" 0603C#1 13200.13,7525 r180 top
C126 "100nF" 0603C#1 12150,7350.13 r270 top
C127 "100nF" 0603C#1 12800,7475 r90 top
C128 "100nF" 0603C#1 12150,7224.87 r90 top
C129 "100nF" 0603C#1 12800,7125 r270 top
C130 "100nF" 0603C#1 12475.13,7100 r180 top
C131 "100nF" 0603C#1 10900,6875 r270 top
C132 "100nF" 0603C#1 12150,7100.13 r270 top
C133 "100nF" 0603C#1 11000,6725 r270 top
C134 "100nF" 0603C#1 10175.13,6075 r180 top
C135 "47pF" 0603C#2 13125,5750 r270 top
CN1 "47151-0051" 0471510051 11200,11410 r180 top locked
CN2 "47151-0051" 0471510051 12050,11410 r180 top
CN3 "SSM-104-L-SH" SSM-104-L-SH 10450,11425 r270 top locked
CN5 "DB9-male CAN connector" DB9/M 9900,10425 r90 top
CN6 "" SIP2#1 12775,9150 r0 top
CN7 "PJS008-2000 (SMS064FF or SMS128FF)" MSD(PJS008) 13635,9175 r90 top
CN9 "" SIP2#2 12425,8825 r270 top
CN10 "" SIP2#2 12600,8825 r270 top
CN11 "" SIP2#2 12775,8825 r270 top
CN12 "DB9-male USART2" DB9/M 9900,9100 r90 top
CN13 "2213S-50G" 2*25P 10350,10725 r0 top locked
CN14 "2213S-50G" 2*25P 13050,10725 r0 top locked
CN15 "FTSH-110-01-L-DV" FTSH-110-01-L-DV 13425,8050 r270 top
CN16 "USB-typeB connector" USB-B 9975,8050 r270 top
CN17 "JTAG" IDC20S 13750,8325 r0 top
CN18 "DC-10B" DC10B 9675.91,6630 r0 top
CN19 "JTAG" 2*3P 10600,6300 r0 top
CN20 "2.8\" LCD connector" MB989 13375,7450 r0 top
CN21 "ST-212-02V" ST-212-02V 13850,5700 r0 top
CN22 "USB-typeB connector" USB-B 9975,5900 r270 top
D1 "BAT60J" SOD-323 11275,9025 r90 top
D2 "BAT60J" SOD-323 11275,8825 r90 top
D3 "BAT60J[N/A]" SOD-323 12400,8575 r0 top
D4 "BAT60J" SOD-323 11775,8250 r90 top
D5 "BAT60J[N/A]" SOD-323 12050,7275 r0 top
D6 "[N/A]" SOT-23#1 11650,6475 r0 top
D7 "Z5V1" SOT-23#1 11825,6475 r0 top
D8 "Z5V1" SOT-23#1 11650,6300 r0 top
D9 "Z5V1" SOT-23#1 11825,6300 r0 top
D10 "Z5V1" SOT-23#1 11650,6125 r0 top
D11 "Z5V1" SOT-23#1 11825,6125 r0 top
JP1 "" SIP2#2 12725,11150 r0 top
JP2 "" SIP2#2 10150,10575 r90 top
JP3 "" SIP3#1 10700,10450 r0 top
JP4 "" SIP3#1 10700,9975 r0 top
JP5 "" SIP3#1 10700,9800 r0 top
JP6 "" SIP3#1 10700,9625 r0 top
JP7 "" SIP3#1 10700,9450 r0 top
JP8 "" SIP2#2 11175,9025 r180 top
JP9 "" SIP2#2 11175,8850 r180 top
JP10 "Header 4X2" 2*4P 10675,7850 r90 top
JP11 "" SIP3#1 11150,7850 r90 top
JP12 "" SIP3#1 11325,7850 r90 top
JP13 "" SIP3#1 11825,7850 r90 top
JP14 "" SIP2#2 12875,7850 r90 top
JP15 "" SIP2#2 11175,8675 r180 top
JP16 "" SIP2#3 12050,7950 r270 top
JP17 "" SIP2#2 12175,10350 r270 top
JP18 "" SIP3#2 12450,9300 r90 top
L1 "BEAD" 0603L 11875,8250 r270 top
L2 "BEAD" 0603L 12950,11100 r180 bottom
L3 "BEAD" 0603L 11975,9775 r270 bottom
L4 "BEAD" 0603L 10675,6800 r0 top
L5 "BEAD" 0603L 10800,6475 r90 top
LD1 "Green" 0603D 11875,5575 r270 top
LD2 "Orange" 0603D 11775,5575 r270 top
LD3 "Red" 0603D 11675,5575 r270 top
LD4 "Blue" 0603D 11575,5575 r270 top
LD5 "Green" 0603D 10975,5450 r270 top
LD6 "Red" 0603D 10975,5250 r270 top
LD7 "HSMF-A201-A00J1" LED2-28*32 9825,5500 r270 top
LD8 "red" 0603D 10975,8250 r90 top
LD9 "Green" 0603D 12425,9150 r90 top
LD10 "SFH409-2" D0.1L 13700,6700 r90 top
MP1 "" markpoint_1.0#1 13550,11575 r0 top
MP2 "" markpoint_1.0#2 13575,11575 r180 bottom
MP3 "" markpoint_1.0#2 9900,5325 r180 bottom
MP4 "" markpoint_1.0#1 9899.94,5299.72 r0 top
R1 "10K" 0603R#1 12675,11500 r90 top
R2 "27K" 0603R#1 12675,11350 r90 top
R3 "1M" 0603R#1 12775,11050 r180 top
R4 "100K[0.1%]" 0603R#1 13200,10925 r0 top
R5 "4K7" 0603R#2 12800,10750 r180 top
R6 "10K" 0603R#1 12800,10650 r180 top
R7 "120" 0603R#1 10150,10425 r270 top
R8 "0" 0603R#1 10950,10350 r0 top
R9 "[N/A]" 0603R#1 10150,10275 r90 top
R10 "0" 0603R#1 10675,10125 r180 top
R11 "10K" 0603R#1 11675,10250 r270 top
R12 "10K" 0603R#1 11750,10250 r270 top
R13 "10K" 0603R#1 11825,10250 r270 top
R14 "0" 0603R#1 12375,10225 r270 top
R15 "1M" 0603R#1 12775,10225 r270 top
R16 "220" 0603R#1 12475,10225 r270 top
R17 "2K5" 0603R#1 12575,10225 r270 top
R18 "820" 0603R#1 12675,10225 r270 top
R19 "0" 0603R#1 10150,10025 r270 top
R20 "100K[0.1%]" 0603R#1 13200,10850 r0 top
R21 "100" 0603R#1 12450,9850 r180 top
R22 "1K" 0603R#1 12300,9350 r0 bottom
R23 "100" 0603R#1 12450,9725 r180 top
R24 "0" 0603R#1 13325,9575 r90 top
R25 "0" 0603R#1 12650,9150 r90 top
R26 "100" 0603R#1 12550,9300 r90 top
R27 "1K8[0.1%]" 0603R#1 12850,9300 r90 top
R28 "10K" 0603R#1 13325,9325 r270 top
R29 "0" 0603R#1 11500,9650 r180 bottom
R30 "PT100" 0805R 12550,9150 r90 top
R31 "2.2k" 0603R#1 11500,9725 r180 bottom
R32 "0" 0603R#1 11875,9175 r90 top
R33 "1K8[0.1%]" 0603R#1 12450,9625 r180 top
R34 "220" 0603R#1 12300,9325 r180 top
R35 "0" 0603R#1 13325,9175 r90 top
R36 "0" 0603R#1 11375,9000 r270 top
R37 "0" 0603R#1 11575,9000 r270 top
R38 "0" 0603R#1 12050,9000 r90 top
R39 "0" 0603R#1 12300,8975 r90 top
R40 "0" 0603R#1 12475,8975 r90 top
R41 "1K8[0.1%]" 0603R#1 12650,9300 r270 top
R42 "0" 0603R#1 12575,8975 r90 top
R43 "0" 0603R#1 12675,8975 r90 top
R44 "1K8[0.1%]" 0603R#1 12750,9300 r270 top
R45 "0" 0603R#1 12775,8975 r90 top
R46 "100K" 0603R#1 10675,8725 r0 top
R47 "100K" 0603R#1 10675,8625 r0 top
R48 "5" 0603R#1 13625,8650 r180 top
R49 "47" 0603R#1 13625,8725 r180 top
R50 "4K7" 0603R#1 12400,8325 r0 top
R51 "0" 0603R#1 10350,8150 r180 top
R52 "N/A" 0603R#1 11275,8250 r90 top
R53 "1K" 0603R#1 11075,8250 r90 top
R54 "0" 0603R#1 11175,8250 r90 top
R55 "0" 0603R#1 11375,8250 r90 top
R56 "0" 0603R#1 11475,8250 r270 top
R57 "[N/A]" 0603R#1 11575,8250 r90 top
R58 "[N/A]" 0603R#1 11675,8250 r90 top
R59 "8.2K" 0603R#1 12500,8225 r270 top
R60 "0" 0603R#1 13025,8125 r180 top
R61 "0" 0603R#1 10175,8150 r0 top
R62 "0" 0603R#1 12600,8225 r270 top
R63 "VT9ON1" PVT901 12775,8225 r180 top
R64 "0" 0603R#1 13175,8125 r0 top
R65 "47K" 0603R#1 10350,8050 r180 top
R66 "36K" 0603R#1 10525,8050 r180 top
R67 "0" 0603R#1 12375,8000 r270 top
R68 "0" 0603R#1 12450,8000 r270 top
R69 "0" 0603R#1 12525,8000 r270 top
R70 "[N/A]" 0603R#1 11875,9900 r90 bottom
R71 "0" 0603R#1 12750,8000 r270 top
R72 "0" 0603R#1 13025,8025 r0 top
R73 "0" 0603R#1 11625,9450 r0 bottom
R74 "0" 0603R#1 13175,8025 r0 top
R75 "0" 0603R#1 10175,8225 r0 top
R76 "1M" 0603R#1 10175,7825 r0 top
R77 "0" 0603R#1 12200,8000 r90 top
R78 "0" 0603R#1 12275,8000 r90 top
R79 "0" 0603R#1 12600,7825 r270 top
R80 "0" 0603R#1 11875,9775 r270 bottom
R81 "0" 0603R#1 12675,8000 r270 top
R82 "0" 0603R#1 11625,9600 r0 bottom
R83 "0" 0603R#1 13175,7925 r0 top
R84 "1K5" 0603R#1 10525,7750 r0 top
R85 "0" 0603R#1 13175,7825 r0 top
R86 "10K" 0603R#1 10350,7750 r180 top
R87 "0" 0603R#1 12200,7825 r90 top
R88 "0" 0603R#1 12275,7825 r90 top
R89 "0" 0603R#1 12375,7825 r270 top
R90 "0" 0603R#1 12525,7825 r270 top
R91 "0" 0603R#1 12450,7825 r270 top
R92 "0" 0603R#1 12600,8000 r90 top
R93 "[N/A]" 0603R#1 11500,9575 r180 bottom
R94 "0" 0603R#1 12675,7825 r270 top
R95 "[N/A]" 0603R#1 11625,9525 r0 bottom
R96 "0" 0603R#1 12750,7825 r270 top
R97 "4K7" 0603R#1 11350,7650 r270 top
R98 "[N/A]" 0603R#1 11675,7650 r90 top
R99 "10K" 0603R#1 11525,7650 r270 top
R100 "1K" 0603R#1 11750,7650 r270 top
R101 "10K" 0603R#1 12925,7625 r90 top
R102 "[N/A]" 0603R#1 11450,7650 r270 top
R103 "10K" 0603R#1 12525,7550 r90 top
R104 "1K8" 0603R#1 13000,7625 r270 top
R105 "1K8" 0603R#1 13075,7625 r270 top
R106 "59K[1%]" 0603R#1 11150,7475 r180 top
R107 "31.6K[1%]" 0603R#1 11300,7375 r0 top
R108 "4K7" 0603R#1 12050,7375 r0 top
R109 "100" 0603R#1 12625,7300 r0 top
R110 "10K" 0603R#1 13200,7375 r0 top
R111 "31.6K[1%]" 0603R#1 11825,7300 r90 top
R112 "4K7" 0603R#1 13200,7150 r0 top
R113 "0" 0603R#1 13625,7050 r180 top
R114 "15K[1%]" 0603R#1 11725,7300 r270 top
R115 "51" 0603R#1 12425,6850 r270 top
R116 "51" 0603R#1 12525,6850 r270 top
R117 "10K" 0603R#1 12925,6775 r270 top
R118 "100" 0603R#1 13250,6775 r90 top
R119 "100" 0603R#1 13325,6775 r90 top
R120 "1K" 0603R#1 12475,11500 r90 bottom
R121 "100[0.1%]" 0603R#1 12300,9425 r0 top
R122 "2K2" 0603R#1 12925,6625 r90 top
R123 "1K" 0603R#1 13175,6625 r90 top
R124 "10K" 0603R#1 13250,6625 r270 top
R125 "22" 0603R#1 13400,6625 r270 top
R126 "100K" 0603R#1 11475,6500 r180 top
R127 "100K" 0603R#1 10875,6300 r90 top
R128 "1K5" 0603R#1 10125,6250 r90 top
R129 "0" 0603R#1 13200,7250 r180 top
R130 "0" 0603R#1 10175,6150 r0 top
R131 "10K" 0603R#1 10400,6250 r270 top
R132 "36K" 0603R#1 10475,6250 r90 top
R133 "100K" 0603R#1 11475,6175 r180 top
R134 "4K7" 0603R#1 11475,6100 r0 top
R135 "0" 0603R#1 11050,9700 r0 bottom
R136 "220" 0603R#1 13275,6100 r90 top
R137 "10K" 0603R#1 10875,6050 r90 top
R138 "4K7" 0603R#1 11475,6025 r180 top
R139 "0" 0603R#1 11200,9600 r0 bottom
R140 "680" 0603R#1 12900,6100 r270 top
R141 "82K" 0603R#1 12975,6100 r270 top
R142 "0" 0603R#1 10175,5900 r0 top
R143 "100" 0603R#1 10425,5875 r0 top
R144 "510" 0603R#1 10800,5925 r270 top
R145 "[N/A]" 0603R#1 10925,5950 r180 top
R146 "680" 0603R#1 11575,5900 r90 top
R147 "510" 0603R#1 11675,5900 r90 top
R148 "0" 0603R#1 11200,9700 r0 bottom
R149 "100" 0603R#1 10425,5775 r0 top
R150 "330" 0603R#1 11800,5900 r270 top
R151 "220K" 0603R#1 11900,5900 r270 top
R152 "100" 0603R#1 12500,5900 r270 top
R153 "0" 0603R#1 10425,5675 r180 top
R154 "510" 0603R#1 10800,5750 r270 top
R155 "[N/A]" 0603R#1 11475,5750 r90 top
R156 "680" 0603R#1 11575,5750 r90 top
R157 "680" 0603R#1 11675,5750 r90 top
R158 "100" 0603R#1 11900,5750 r90 top
R159 "0" 0603R#1 12475,11350 r90 bottom
R160 "0" 0603R#3 10525,5600 r270 top
R162 "100" 0603R#1 12500,5750 r90 top
R163 "0" 0603R#1 13200,7450 r0 top
R164 "2K2" 0603R#1 13050,5750 r270 top
R165 "100" 0603R#1 13275,5750 r270 top
R166 "47K" 0603R#1 13325,5925 r90 top
R167 "4K7" 0603R#1 12600,5750 r90 top
R168 "100K" 0603R#1 12675,5750 r90 top
R169 "100K" 0603R#1 12750,5750 r270 top
R170 "18K" 0603R#1 12900,5750 r90 top
R171 "15K" 0603R#1 12825,5750 r270 top
R172 "47K" 0603R#1 11300,11550 r270 bottom
R173 "47K" 0603R#1 11225,11550 r270 bottom
R174 "0" 0603R#1 12175,11550 r90 bottom
R175 "1M" 0603R#1 12250,11400 r270 bottom
R176 "4K7" 0603R#1 12675,11500 r90 bottom
R177 "2M[1%]" 0603R#1 12775,10925 r180 bottom
R178 "2M[1%]" 0603R#1 12775,10850 r180 bottom
R179 "3K3" 0603R#1 12775,11000 r0 bottom
R180 "4K7" 0603R#1 12775,10775 r180 bottom
R181 "15K" 0603R#1 12400,10350 r180 bottom
R182 "10K" 0603R#1 11100,10350 r180 top
R183 "[N/A]" 0603R#1 12400,10200 r180 bottom
R184 "100K" 0603R#1 12775,10225 r90 bottom
R185 "0" 0603R#1 10725,10150 r270 bottom
R186 "[N/A]" 0603R#1 10875,10150 r90 bottom
R187 "0" 0603R#1 11050,9775 r0 bottom
R188 "4K7" 0603R#1 12500,10225 r270 bottom
R189 "[N/A]" 0603R#1 10800,10150 r270 bottom
R190 "0" 0603R#1 11050,10000 r0 bottom
R191 "[N/A]" 0603R#1 11050,9850 r180 bottom
R192 "[N/A]" 0603R#1 11050,9925 r0 bottom
R193 "22K[1%]" 0603R#1 12550,9900 r90 bottom
R194 "1K[1%]" 0603R#1 12650,9900 r90 bottom
R195 "0" 0603R#1 10950,10150 r90 bottom
R196 "0" 0603R#1 12325,9925 r90 bottom
R197 "47" 0603R#1 12325,9775 r270 bottom
R198 "220K[1%]" 0603R#1 12750,9900 r90 bottom
R199 "0" 0603R#1 11050,9600 r0 bottom
R200 "22K[1%]" 0603R#1 12550,9750 r90 bottom
R201 "0" 0603R#1 11925,9575 r270 bottom
R203 "820" 0603R#1 11825,9650 r90 bottom
R204 "1K8[0.1%]" 0603R#1 12825,9350 r180 bottom
R205 "220K[1%]" 0603R#1 12650,9750 r270 bottom
R206 "510" 0603R#1 12300,9275 r180 bottom
R207 "1K8[0.1%]" 0603R#1 12550,9250 r270 bottom
R208 "1K8[0.1%]" 0603R#1 12825,9275 r0 bottom
R209 "1K8[0.1%]" 0603R#1 12625,9250 r90 bottom
R210 "0" 0603R#1 11175,9275 r90 top
R211 "510" 0603R#1 11075,9275 r90 top
R212 "0" 0603R#1 12250,8625 r0 bottom
R213 "1K8" 0603R#1 12600,8625 r180 bottom
R214 "4K7" 0603R#1 12775,8525 r0 bottom
R215 "0" 0603R#1 12775,8625 r0 bottom
R216 "10K" 0603R#1 10950,8775 r0 top
R217 "0" 0603R#1 12250,8525 r180 bottom
R218 "0" 0603R#1 12400,8525 r180 bottom
R219 "10K" 0603R#1 12600,8425 r180 bottom
R220 "0" 0603R#1 12250,8425 r0 bottom
R221 "1K8" 0603R#1 12400,8325 r180 bottom
R222 "0" 0603R#1 12400,8425 r180 bottom
R223 "[N/A]" 0603R#1 13600,8225 r180 bottom
R224 "[N/A]" 0603R#1 13600,8325 r0 bottom
R225 "[N/A]" 0603R#1 13600,8125 r0 bottom
R226 "[N/A]" 0603R#1 13600,7925 r180 bottom
R227 "[N/A]" 0603R#1 13600,8025 r0 bottom
R228 "[N/A]" 0603R#1 13600,7825 r0 bottom
R229 "10K" 0603R#1 13600,7750 r180 bottom
R230 "[N/A]" 0603R#1 13600,7600 r180 bottom
R231 "[N/A]" 0603R#1 13600,7675 r0 bottom
R232 "10K" 0603R#1 13600,7525 r180 bottom
R233 "100K" 0603R#1 12625,7500 r180 top
R234 "10K" 0603R#1 13600,7425 r180 bottom
R235 "0" 0603R#1 12800,7300 r90 top
R236 "0" 0603R#1 12800,6975 r90 top
R237 "0" 0603R#1 10900,6725 r270 top
R238 "[N/A]" 0603R#1 10800,6725 r270 top
R240 "0" 0603R#1 13325,6625 r270 top
R241 "0" 0603R#1 13125,6100 r90 top
R242 "0" 0603R#1 10525,5925 r90 top
R243 "0" 0603R#1 10725,5925 r90 top
R244 "1K[1%]" 0603R#1 10725,5750 r90 top
R245 "1K" 0603R#1 13200,5750 r90 top
R246 "2.67K[1%]" 0603R#1 10525,5750 r270 top
R247 "0" 0603R#1 13625,7150 r180 top
R248 "0" 0603R#3 10675,10350 r0 top
R249 "0" 0603R#3 11050,9500 r0 bottom
RS1 "22" RES8B_0402 11475,6375 r270 top
RV1 "[N/A]" 3314-J 13775,6475 r180 top
RV2 "3386P-503H[5%]" 3296W 10225,5325 r180 top
RV3 "10K" 3296W 10650,5325 r180 top
S1 "Slider 3 pos" SLIDER3-2(50) 10622.5,10640 r0 top
SB1 "" JP2_SMD 11225,11400 r270 bottom
SB2 "" JP2_SMD 11300,11400 r270 bottom
SB3 "" JP2_SMD 12175,11400 r90 bottom
SB4 "" JP2_SMD 12250,11550 r270 bottom
SB5 "" JP2_SMD 12950,11175 r0 bottom
SB6 "" JP2_SMD 13050,10850 r90 bottom
SB7 "" JP2_SMD 12950,10725 r180 bottom
SB8 "" JP2_SMD 11675,10200 r270 bottom
SB9 "" JP2_SMD 11725,10200 r270 bottom
SB10 "" JP2_SMD 11775,10200 r270 bottom
SB11 "" JP2_SMD 11825,10200 r270 bottom
SB12 "" JP2_SMD 12100,10000 r0 bottom
SB13 "" JP2_SMD 12150,9750 r180 bottom
SB14 "" JP2_SMD 12150,9800 r180 bottom
SB15 "" JP2_SMD 12025,9775 r90 bottom
SB16 "" JP2_SMD 12150,9650 r0 bottom
SB17 "" JP2_SMD 12150,9700 r0 bottom
SB18 "" JP2_SMD 12150,9600 r180 bottom
SB19 "" JP2_SMD 12300,9525 r0 bottom
SB20 "" JP2_SMD 12300,9225 r0 bottom
SB21 "" JP2_SMD 12925,9200 r180 bottom
SB22 "" JP2_SMD 12300,9425 r0 bottom
SB23 "" JP2_SMD 11850,9000 r90 bottom
SB24 "" JP2_SMD 12000,9000 r270 bottom
SB25 "" JP2_SMD 11375,9000 r270 bottom
SB26 "" JP2_SMD 11475,9000 r270 bottom
SB27 "" JP2_SMD 12600,8325 r180 bottom
SB28 "" JP2_SMD 13400,6775 r270 bottom
SW1 "09.03290.01" SIP3#1 10675,8425 r0 top
T1 "9012" SOT-23#2 12525,11500 r0 top
T2 "2N7002" SOT-23#1 12525,11350 r0 top
T3 "9013" SOT-23#1 12300,9200 r180 top
T4 "9013" SOT-23#1 10350,7900 r180 top
T5 "9013" SOT-23#1 10525,7900 r180 top
T6 "9013" SOT-23#1 13050,6775 r0 top
T7 "9013" SOT-23#1 13050,6625 r180 top
T8 "9013" SOT-23#1 10275,6250 r90 top
TP1 "RIGHT" TP#1 13375,11000 r180 top
TP2 "Ground" TP#2 10150,10875 r0 top
TP3 "LEFT" TP#1 13375,10550 r180 top
TP4 "SD_VREF" TP#2 11950,10150 r0 top
TP5 "SAR_VREF" TP#2 12125,8975 r0 top
TP6 "VDDA" TP#2 12050,8250 r0 top
TP7 "+3V3" TP#2 12225,8225 r0 top
TP8 "5V" TP#2 10525,8150 r0 top
TP9 "VDD_ADJ" TP#2 11500,8050 r0 top
TP10 "VDD" TP#2 11675,8050 r0 top
TP12 "+1V8" TP#2 11500,7850 r0 top
TP13 "2V5" TP#2 11675,7850 r0 top
TP15 "MIC+" TP#2 13100,5550 r0 top
TP16 "MIC_OUT" TP#2 13275,5550 r90 top
TR1 "FDN327N" SOT-23#1 12400,8450 r270 top
TR2 "FDN327N" SOT-23#1 12050,7150 r0 top
TR3 "BSN20" SOT-23#1 13200,7025 r180 top
TS1 "TS_PAD" TS_PAD#1 13700,11350 r90 top
TS2 "TS_PAD" TS_PAD#2 13700,10100 r90 top
U1 "STMPS2141STR@54" SOT-23-5L 12925,11350 r0 top
U2 "INA333" MSOP8 12875,10875 r90 top
U3 "TSV624AIPT" TSSOP14 12650,10400 r90 top
U4 "SN65HVD230" SO8 10925,10200 r270 top
U5 "MPX2102" MPAK 12575,10025 r180 top
U6 "TVS632AIDT" SO8 12700,9725 r0 top
U7 "TSV631AILT" SOT-23-5L 12625,9475 r0 top
U8 "TSV631AILT" SOT-23-5L 12825,9475 r0 top
U9 "Goldfish_256K_TQFP100" IC149-100-025-B5 11725,9650 r0 top locked
U10 "ST3241EBPR" SSOP28 10825,9000 r0 top
U11 "SN74LVC2T45DCUT" VSSOP8 10850,8675 r0 top
U12 "TFDU6300" IR_VISHAY3 13775,8775 r270 top
U13 "USBLC6-2P6 (optional)" SOT-666 10175,8050 r90 top
U14 "STLM75M2E" SO8 12650,8475 r270 top
U15 "SN74LVC2T45DCUT" VSSOP8 13250,7625 r0 top
U16 "ST1L05BPUR" DFN6(3X3) 11300,7500 r180 top
U17 "ST1L05BPUR" DFN6(3X3) 11750,7500 r180 top
U18 "M24M01-HRMN6T" SO8 12975,7375 r0 top
U19 "CS43L22" QFN40(6*6) 12375,7300 r0 top
U20 "BNX002-01" BNX001 9800,7150 r180 top
U21 "M95M01-RMN6TP" SO8 12975,7025 r0 top
U22 "TSOP34836" TSOP348 13825,6925 r90 top
U23 "SN74LVC2T45DCUT" VSSOP8 11000,6875 r90 top
U24 "LD1117S25TR" SOT-223 12125,6675 r90 top
U25 "LD1086D2M33" D2PAK/A 10225,6600 r180 top
U26 "ZEN056V130A24LS" polyzen 10200,6925 r270 top
U27 "STM32F103C8T6" LQFP48 11150,6225 r0 top
U28 "KECG2740TBL" KEC2740 13775,6200 r90 top
U29 "USBLC6-2P6 (optional)" SOT-666 10175,6000 r90 top
U30 "KSS-1508 or KSSG1708" KS1708 11450,6925 r270 top
U32 "TS461CLT" SOT-23-5L 13100,5925 r0 top
U33 "TS3702IPT" TSSOP8(6.4) 10625,5850 r0 top
U34 "MT008-A" JOY 12650,5300 r315 top
X1 "MC306-G-06Q-32.768 (manufacturer KDS)" SM8 11500,8825 r180 top
X2 "ESA8.00000F20D25F(with socket)" XTAL_socket 11975,8825 r0 top
X3 "8MHz" SMT_XTAL 11125,5800 r180 top
Z1 "SMAJ5.0A-TR" 1R1C 10200,7200 r180 top

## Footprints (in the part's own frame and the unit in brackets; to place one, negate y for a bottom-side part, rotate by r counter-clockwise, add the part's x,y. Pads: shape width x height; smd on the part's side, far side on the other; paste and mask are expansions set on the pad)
1R1C [mm]
  rect 2.3x1.75 smd mask+0.102: 1(1.9,0) 2(-1.9,0)
  silkscreen extent -2.2,-1.5 2.2,1.5
2*3P [mil]
  round 60 hole 40 mask+4: 1(0,0) 2(100,0) 3(0,-100) 4(100,-100) 5(0,-200)
  silkscreen extent -50,-250 150,50
2*4P [mil]
  round 60 hole 40 mask+4: 1(0,0) 2(100,0) 3(0,-100) 4(100,-100) 5(0,-200) 6(100,-200) 7(0,-300) 8(100,-300)
  silkscreen extent -50,-350 150,50
2*25P [mil]
  round 60 hole 40 mask+4: 1(0,0) 2(100,0) 3(0,-100) 4(100,-100) 5(0,-200) 6(100,-200) 7(0,-300) 8(100,-300) 9(0,-400) 10(100,-400) 11(0,-500) 12(100,-500) 13(0,-600) 14(100,-600) 15(0,-700) 16(100,-700) 17(0,-800) 18(100,-800) 19(0,-900) 20(100,-900) 21(0,-1000) 22(100,-1000) 23(0,-1100) 24(100,-1100) 25(0,-1200) 26(100,-1200) 27(0,-1300) 28(100,-1300) 29(0,-1400) 30(100,-1400) 31(0,-1500) 32(100,-1500) 33(0,-1600) 34(100,-1600) 35(0,-1700) 36(100,-1700) 37(0,-1800) 38(100,-1800) 39(0,-1900) 40(100,-1900) 41(0,-2000) 42(100,-2000) 43(0,-2100) 44(100,-2100) 45(0,-2200) 46(100,-2200) 47(0,-2300) 48(100,-2300) 49(0,-2400) 50(100,-2400)
  silkscreen extent -50,-2450 150,50
0603C#1 [mil]
  rect 30x30 smd mask+4: 1(27.56,0.28) 2(-27.44,0.28)
  silkscreen extent -50,-20 50,20
0603C#2 [mil]
  rect 30x30 smd mask+4: 1(27.5,0) 2(-27.5,0)
  silkscreen extent -50,-20 50,20
0603C#3 [mil]
  rect 30x30 smd: 1(27.5,0) 2(-27.5,0)
  silkscreen extent -50,-20 50,20
0603D [mil]
  rect 30x30 smd mask+4: 1(27.5,0) 2(-27.5,0)
  silkscreen extent -50,-25 55,25
0603L [mil]
  rect 30x30 smd mask+4: 1(27.5,0) 2(-27.5,0)
  silkscreen extent -50,-20 50,20
0603R#1 [mil]
  rect 30x30 smd mask+4: 1(27.5,0) 2(-27.5,0)
  silkscreen extent -50,-20 50,20
0603R#2 [mil]
  rect 30x30 smd mask+4: 1(27.56,0.28) 2(-27.44,0.28)
  silkscreen extent -50,-20 50,20
0603R#3 [mil]
  rect 30x30 smd: 1(27.5,0) 2(-27.5,0)
  silkscreen extent -50,-20 50,20
0805C#1 [mil]
  rect 40x50 smd mask+4: 1(40,0) 2(-40,0)
  silkscreen extent -70,-35 70,35
0805C#2 [mil]
  rect 40x50 smd: 1(40,0) 2(-40,0)
  silkscreen extent -70,-35 70,35
0805R [mil]
  rect 40x50 smd mask+4: 1(40,0) 2(-40,0)
  silkscreen extent -70,-35 70,35
1206C [mil]
  rect 50x60 smd mask+4: 1(60,0) 2(-60,0)
  silkscreen extent -95,-40 95,40
3296W [mil]
  round 50 hole 28 mask+4: 1(-100,0) 2(0,100) 3(100,0)
  silkscreen extent -190,-190 190,190
3314-J [mm]
  rect 2x1.3 smd mask+0.102: 1(2,1.15) 3(2,-1.15)
  rect 2x2 smd mask+0.102: 2(-2,0)
  silkscreen extent -2.54,-2.54 2.54,2.54
0471510051 [mm]
  round 0.9 hole 0.9 mask+0.102: 0(-7.25,-1.674) 0(-7.25,-1.446) 0(-7.25,-1.141) 0(-7.25,-0.379) 0(-7.25,-0.1) 0(-7.25,0.205) 0(-7.25,-7.137) 0(-7.25,-6.909) 0(-7.25,-6.502) 0(-7.25,-6.299) 0(7.25,-7.137) 0(7.25,-6.909) 0(7.25,-6.502) 0(7.25,-6.299) 0(7.25,-1.676) 0(7.25,-1.448) 0(7.25,-1.143) 0(7.25,-0.381) 0(7.25,-0.102) 0(7.264,0.203)
  oval 1.5x2.3 hole 0.9 mask+0.102: 0(-7.25,-6.72) 0(7.25,-6.72)
  oval 1.5x3.3 hole 0.9 mask+0.102: 0(-7.25,-0.76) 0(7.25,-0.762)
  rect 0.3x2.6 smd mask+0.102: 1(4.5,0) 2(4,0) 3(3.5,0) 4(3,0) 5(2.5,0) 6(2,0) 7(1.5,0) 8(1,0) 9(0.5,0) 10(0,0) 11(-0.5,0) 12(-1,0) 13(-1.5,0) 14(-2,0) 15(-2.5,0) 16(-3,0) 17(-3.5,0) 18(-4,0) 19(-4.5,0)
  silkscreen extent -7.5,-10.1 7.5,1.3
BNX001 [mm]
  round 1.8 hole 1.4 mask+0.102: 1(2.5,2.5) 2(-2.5,2.5) 3(2.5,-2.5) 4(0,0) 5(5,0) 6(-2.5,-2.5)
  silkscreen extent -5,-5 5.76,5
C200M [mil]
  rect 100x80 smd mask-19.68: 1(90,0) 2(-90,0)
  silkscreen extent -90,-105 95,105
C310M [mil]
  rect 200x120 smd mask-23.62: 1(125,0) 2(-125,0)
  silkscreen extent -163,-163 163,163
D0.1L [mil]
  round 50 hole 30 mask+4: 1(-50,0) 2(50,0)
  silkscreen extent -84,-361 84,79
D2PAK/A [mm]
  rect 2.8x1 smd mask+0.102: 1(-11.4,2.54) 2(-11.4,0)
  rect 8x10.2 smd mask+0.102: 2(0,0)
  rect 2.8x1.42 smd mask+0.102: 3(-11.4,-2.54)
  silkscreen extent -6.35,-5.08 4.06,5.08
DB9/M [mil]
  round 50 hole 50 mask+4: 0(-538,55) 0(-523,55) 0(-508,55) 0(-493,55) 0(-478,55) 0(-463,55) 0(-448,55) 0(448,55) 0(463,55) 0(478,55) 0(493,55) 0(508,55) 0(523,55) 0(538,55)
  oval 170x80 hole 50 mask+4: 0(-493,55) 0(493,55)
  rect 70x80 hole 38 mask+4: 1(218,0)
  oval 70x80 hole 38 mask+4: 2(109,0) 3(0,0) 4(-109,0) 5(-218,0) 6(164,110) 7(55,110) 8(-54,110) 9(-163,110)
  silkscreen extent -618,-100 618,410
DC10B [mil]
  round 45 hole 30 mask+4: 1(244.09,-40) 1(244.09,-20) 1(244.09,20) 1(244.09,40) 2(82.05,-196.85) 2(102.05,-196.85) 2(142.05,-196.85) 2(162.05,-196.85) 3(0,-40) 3(0,-20) 3(0,20) 3(0,40)
  oval 80x180 hole 30 mask+4: 1(244.09,0) 3(0,0)
  oval 180x80 hole 30 mask+4: 2(122.05,-196.85)
  silkscreen extent -175,-170 290,180
DFN6(3X3) [mm]
  rect 2x1.2 smd mask+0.102: 0(0,0)
  rect 0.45x0.5 smd mask+0.102: 1(-0.95,-1.3) 2(0,-1.3) 3(0.95,-1.3) 4(0.95,1.3) 5(0,1.3) 6(-0.95,1.3)
  silkscreen extent -1.5,-1.3 1.5,1.3
FTSH-110-01-L-DV [mil]
  round 25 hole 38 unplated mask+4: 0(-200,0) 0(200,0)
  rect 25x100 smd mask+4: 1(-225,-85) 2(-225,85) 3(-175,-85) 4(-175,85) 5(-125,-85) 6(-125,85) 7(-75,-85) 8(-75,85) 9(-25,-85) 10(-25,85) 11(25,-85) 12(25,85) 13(75,-85) 14(75,85) 15(125,-85) 16(125,85) 17(175,-85) 18(175,85) 19(225,-85) 20(225,85)
  silkscreen extent -275,-102 275,102
IC149-100-025-B5 [mm]
  rect 1x2.5 smd rot 45 mask+0.102: 0(-8.1,-8.1) 0(8.1,8.1)
  rect 1x2.5 smd rot 135 mask+0.102: 0(-8.1,8.1) 0(8.1,-8.1)
  round 1.5 hole 1.5 unplated mask+0.102: 0(0,-5) 0(0,5)
  rect 0.25x1.65 smd mask+0.102: 1(-6,-7.725) 2(-5.5,-7.725) 3(-5,-7.725) 4(-4.5,-7.725) 5(-4,-7.725) 6(-3.5,-7.725) 7(-3,-7.725) 8(-2.5,-7.725) 9(-2,-7.725) 10(-1.5,-7.725) 11(-1,-7.725) 12(-0.5,-7.725) 13(0,-7.725) 14(0.5,-7.725) 15(1,-7.725) 16(1.5,-7.725) 17(2,-7.725) 18(2.5,-7.725) 19(3,-7.725) 20(3.5,-7.725) 21(4,-7.725) 22(4.5,-7.725) 23(5,-7.725) 24(5.5,-7.725) 25(6,-7.725) 51(6,7.725) 52(5.5,7.725) 53(5,7.725) 54(4.5,7.725) 55(4,7.725) 56(3.5,7.725) 57(3,7.725) 58(2.5,7.725) 59(2,7.725) 60(1.5,7.725) 61(1,7.725) 62(0.5,7.725) 63(0,7.725) 64(-0.5,7.725) 65(-1,7.725) 66(-1.5,7.725) 67(-2,7.725) 68(-2.5,7.725) 69(-3,7.725) 70(-3.5,7.725) 71(-4,7.725) 72(-4.5,7.725) 73(-5,7.725) 74(-5.5,7.725) 75(-6,7.725)
  rect 1.65x0.25 smd mask+0.102: 26(7.725,-6) 27(7.725,-5.5) 28(7.725,-5) 29(7.725,-4.5) 30(7.725,-4) 31(7.725,-3.5) 32(7.725,-3) 33(7.725,-2.5) 34(7.725,-2) 35(7.725,-1.5) 36(7.725,-1) 37(7.725,-0.5) 38(7.725,0) 39(7.725,0.5) 40(7.725,1) 41(7.725,1.5) 42(7.725,2) 43(7.725,2.5) 44(7.725,3) 45(7.725,3.5) 46(7.725,4) 47(7.725,4.5) 48(7.725,5) 49(7.725,5.5) 50(7.725,6) 76(-7.725,6) 77(-7.725,5.5) 78(-7.725,5) 79(-7.725,4.5) 80(-7.725,4) 81(-7.725,3.5) 82(-7.725,3) 83(-7.725,2.5) 84(-7.725,2) 85(-7.725,1.5) 86(-7.725,1) 87(-7.725,0.5) 88(-7.725,0) 89(-7.725,-0.5) 90(-7.725,-1) 91(-7.725,-1.5) 92(-7.725,-2) 93(-7.725,-2.5) 94(-7.725,-3) 95(-7.725,-3.5) 96(-7.725,-4) 97(-7.725,-4.5) 98(-7.725,-5) 99(-7.725,-5.5) 100(-7.725,-6)
  silkscreen extent -6.73,0 6.73,6.73
IDC20S [mil]
  round 60 hole 40 mask+4: 1(0,0) 2(100,0) 3(0,-100) 4(100,-100) 5(0,-200) 6(100,-200) 7(0,-300) 8(100,-300) 9(0,-400) 10(100,-400) 11(0,-500) 12(100,-500) 13(0,-600) 14(100,-600) 15(0,-700) 16(100,-700) 17(0,-800) 18(100,-800) 19(0,-900) 20(100,-900)
  silkscreen extent -125,-1100 250,200
IR_VISHAY3 [mm]
  rect 0.5x2 smd mask+0.102: 1(3.325,0) 2(2.375,0) 3(1.425,0) 4(0.475,0) 5(-0.475,0) 6(-1.425,0) 7(-2.375,0) 8(-3.325,0)
  silkscreen extent -4.18,-1.1 4.33,4.17
JOY [mil]
  rect 40x70 smd mask+4: 0(-140,0) 0(145,0) 1(-55.12,-122.05) 2(0,-122.05) 3(55.12,-122.05) 4(55.12,122.05) 5(0,122.05) 6(-55.12,122.05)
  round 27.56 hole 27.56 unplated mask+4: H(-74.8,0)
  round 39.37 hole 39.37 unplated mask+4: H(74.8,0)
  silkscreen extent -141,-150 146,150
JP2_SMD [mil]
  oct 15x30 smd rot 45 mask+4: 1(-18,-8) 2(18,7)
  oct 15.75x30 smd rot 135 mask+4: 1(-18,8)
  rect 26x26 smd rot 45 mask+4: 2(13,0)
  oct 15x30 smd rot 135 mask+4: 2(18,-7)
KEC2740 [mm]
  round 1.27 hole 0.762 mask+0.102: 1(-1,-0.95) 2(-1,0.95)
  silkscreen extent -3,-3 3,3
KS1708 [mil]
  round 60 hole 40 mask+4: 1(-149.61,0) 2(149.61,0)
  silkscreen extent -335,-334 335,335
LED2-28*32 [mm]
  rect 1.1x1.5 smd mask+0.102: 1(-0.75,-1.5) 2(-0.75,1.5) 3(0.75,1.5) 4(0.75,-1.5)
  silkscreen extent -1.27,-0.64 1.27,0.64
LI1220_1 [mm]
  round 1.1 hole 1.1 unplated mask+0.102: 0(-3.75,0)
  round 1.5 hole 1.5 unplated mask+0.102: 0(3.75,0.025)
  oct 4x2.5 smd mask+0.102: 1(8.255,0) 2(-8.128,0)
  silkscreen extent -7.57,-7.62 7.57,7.62
LQFP48 [mm]
  rect 0.2x1 smd mask+0.102: 1(-2.75,-4.25) 2(-2.25,-4.25) 3(-1.75,-4.25) 4(-1.25,-4.25) 5(-0.75,-4.25) 6(-0.25,-4.25) 7(0.25,-4.25) 8(0.75,-4.25) 9(1.25,-4.25) 10(1.75,-4.25) 11(2.25,-4.25) 12(2.75,-4.25) 25(2.75,4.25) 26(2.25,4.25) 27(1.75,4.25) 28(1.25,4.25) 29(0.75,4.25) 30(0.25,4.25) 31(-0.25,4.25) 32(-0.75,4.25) 33(-1.25,4.25) 34(-1.75,4.25) 35(-2.25,4.25) 36(-2.75,4.25)
  rect 1x0.2 smd mask+0.102: 13(4.25,-2.75) 14(4.25,-2.25) 15(4.25,-1.75) 16(4.25,-1.25) 17(4.25,-0.75) 18(4.25,-0.25) 19(4.25,0.25) 20(4.25,0.75) 21(4.25,1.25) 22(4.25,1.75) 23(4.25,2.25) 24(4.25,2.75) 37(-4.25,2.75) 38(-4.25,2.25) 39(-4.25,1.75) 40(-4.25,1.25) 41(-4.25,0.75) 42(-4.25,0.25) 43(-4.25,-0.25) 44(-4.25,-0.75) 45(-4.25,-1.25) 46(-4.25,-1.75) 47(-4.25,-2.25) 48(-4.25,-2.75)
  silkscreen extent -3.81,-3.81 3.81,3.81
markpoint_1.0#1 [mil]
  round 40 smd mask+4: 0(0.06,0.28)
markpoint_1.0#2 [mil]
  round 40 smd: 0(0,0)
MB989 [mil]
  round 125.98 hole 125.98 mask+4: 0(-3200,-1725) 0(-3050,-1465)
  round 125.98 hole 125.98 unplated mask+4: 0(-3198.94,125) 0(-3050,-45)
  round 60 hole 40 mask+4: 1(0,0) 2(100,0) 3(0,-100) 4(100,-100) 5(0,-200) 6(100,-200) 7(0,-300) 8(100,-300) 9(0,-1000) 10(100,-1000) 11(0,-1100) 12(100,-1100) 13(0,-1200) 14(100,-1200) 15(0,-1300) 16(100,-1300)
  silkscreen extent -3300,-1825 175,225
MPAK [mil]
  rect 60x18 smd mask+4: 1(220,75) 2(220,25) 3(220,-25) 4(220,-75)
  rect 60x130 smd mask+4: 5(-215,0)
  silkscreen extent -225,-120 235,115
MSD(PJS008) [mm]
  rect 1.4x3.429 smd mask+0.102: 0(-3.503,-7.357)
  rect 1.6x3.5 smd mask+0.102: 0(-3.4,3.65)
  rect 1.5x3.1 smd mask+0.102: 0(11.45,-7.35)
  rect 1.2x3.1 smd mask+0.102: 0(11.6,4.15)
  rect 0.8x1.6 smd mask+0.102: 1(1.475,5.8) 2(2.575,5.8) 3(3.675,5.8) 4(4.775,5.8) 5(5.875,5.8) 6(6.975,5.8) 7(8.075,5.8) 8(9.175,5.8)
  rect 0.85x1.6 smd mask+0.102: 9(10.325,5.8)
  rect 1.95x1.4 smd mask+0.102: 10(11.225,-4.4)
  round 0.7 hole 0.7 unplated mask+0.102: H(0,0) H(7.55,0)
  silkscreen extent -3.81,-9.28 11.43,5.07
MSOP8 [mm]
  rect 0.3x0.9 smd mask+0.102: 1(-0.975,-2.151) 2(-0.325,-2.151) 3(0.325,-2.151) 4(0.975,-2.151) 5(0.975,2.151) 6(0.325,2.151) 7(-0.325,2.151) 8(-0.975,2.151)
  silkscreen extent -1.32,-1.36 1.32,1.36
PB10 [mm]
  rect 1.5x1 smd paste+0.381 mask+0: 1(-4.5,-2.222) 2(-4.5,2.222) 3(4.5,2.222) 4(4.5,-2.222)
  silkscreen extent -3.17,-3.17 3.17,3.17
polyzen [mm]
  rect 0.8x2.21 smd mask+0.102: 1(1.714,0)
  rect 0.7x0.94 smd mask+0.102: 2(-1.714,-0.635) 3(-1.714,0.635)
  silkscreen extent -1.97,-2.03 2.1,2.03
PVT901 [mil]
  round 60 hole 30 mask+4: 1(0,50) 2(0,-50)
  silkscreen extent -92,-98 92,98
QFN40(6*6) [mm]
  rect 4x4 smd mask+0.102: 0(0,0)
  rect 0.6x0.2 smd mask+0.102: 1(-2.87,2.25) 2(-2.87,1.75) 3(-2.87,1.25) 4(-2.87,0.75) 5(-2.87,0.25) 6(-2.87,-0.25) 7(-2.87,-0.75) 8(-2.87,-1.25) 9(-2.87,-1.75) 10(-2.87,-2.25) 21(2.87,-2.25) 22(2.87,-1.75) 23(2.87,-1.25) 24(2.87,-0.75) 25(2.87,-0.25) 26(2.87,0.25) 27(2.87,0.75) 28(2.87,1.25) 29(2.87,1.75) 30(2.87,2.25)
  rect 0.2x0.6 smd mask+0.102: 11(-2.25,-2.87) 12(-1.75,-2.87) 13(-1.25,-2.87) 14(-0.75,-2.87) 15(-0.25,-2.87) 16(0.25,-2.87) 17(0.75,-2.87) 18(1.25,-2.87) 19(1.75,-2.87) 20(2.25,-2.87) 31(2.25,2.87) 32(1.75,2.87) 33(1.25,2.87) 34(0.75,2.87) 35(0.25,2.87) 36(-0.25,2.87) 37(-0.75,2.87) 38(-1.25,2.87) 39(-1.75,2.87) 40(-2.25,2.87)
  silkscreen extent -3,-3 3,3
RES8B_0402 [mil]
  rect 10x15 smd mask+4: 1(-68.9,-31) 2(-68.9,31) 3(-49.21,-31) 4(-49.21,31) 5(-29.53,-31) 6(-29.53,31) 7(-9.84,-31) 8(-9.84,31) 9(9.84,-31) 10(9.84,31) 11(29.53,-31) 12(29.53,31) 13(49.21,-31) 14(49.21,31) 15(68.9,-31) 16(68.9,31)
  silkscreen extent -83,-20 83,20
SIP2#1 [mil]
  oval 40x50 hole 30 mask+4: 1(0,0) 2(50,0)
  silkscreen extent -50,-50 100,50
SIP2#2 [mil]
  round 60 hole 40 mask+4: 1(0,0) 2(100,0)
  silkscreen extent -50,-50 150,50
SIP2#3 [mil]
  round 60 hole 40: 1(0,0) 2(100,0)
  silkscreen extent -50,-50 150,50
SIP3#1 [mil]
  rect 60x60 hole 40 mask+4: 1(0,0)
  round 60 hole 40 mask+4: 2(100,0) 3(200,0)
  silkscreen extent -50,-50 250,50
SIP3#2 [mil]
  rect 60x60 hole 40: 1(0,0)
  round 60 hole 40: 2(100,0) 3(200,0)
  silkscreen extent -50,-50 250,50
SLIDER3-2(50) [mil]
  silkscreen extent 0,0 1965,374
SM8 [mm]
  rect 1.9x1.3 smd mask+0.102: 1(-2.75,-1.6) 2(2.75,-1.6) 3(2.75,1.6) 4(-2.75,1.6)
  silkscreen extent -4.44,-1.91 4.44,1.91
SMT_XTAL [mil]
  rect 150x50 smd mask-11.81: 1(-195,0) 2(195,0)
  silkscreen extent -214,-89 214,89
SO8 [mil]
  rect 20x60 smd mask+4: 1(-75,-112.5) 2(-25,-112.5) 3(25,-112.5) 4(75,-112.5) 5(75,112.5) 6(25,112.5) 7(-25,112.5) 8(-75,112.5)
  silkscreen extent -105,-53 105,48
SOD-323 [mm]
  rect 0.6x0.45 smd mask+0.102: 1(1.143,0) 2(-1.143,0)
  silkscreen extent -0.67,-0.57 0.67,0.57
SOT-23#1 [mil]
  rect 36x36 smd mask+4: 1(40,37.5) 2(40,-37.5)
  rect 50x36 smd mask+4: 3(-40,0.5)
  silkscreen extent -45,-58 45,58
SOT-23#2 [mil]
  rect 36x36 smd: 1(40,37.5) 2(40,-37.5)
  rect 50x36 smd: 3(-40,0.5)
  silkscreen extent -45,-58 45,58
SOT-23-5L [mil]
  rect 30x16 smd mask+4: 1(-53.15,37.4) 2(-53.15,0) 3(-53.15,-37.4) 4(53.15,-37.4) 5(53.15,37.4)
  silkscreen extent -33,-58 32,57
SOT-223 [mil]
  rect 80x40 smd mask+4: 1(110,-90.55) 2(110,0) 3(110,90.55)
  rect 90x120 smd mask+4: 2(-110,0)
  silkscreen extent -50,-126 50,134
SOT-666 [mil]
  rect 11x40 smd mask+4: 1(-19.69,-31.3) 2(0,-31.3) 3(19.69,-31.3) 4(19.69,31.3) 5(0,31.3) 6(-19.69,31.3)
  silkscreen extent -35,-32 35,32
SSM-104-L-SH [mm]
  round 1.2 hole 1.2 unplated mask+0.102: 0(-2.54,0) 0(2.54,0)
  rect 1x2 smd mask+0.102: 1(-3.81,5.143) 2(-1.27,5.143) 3(1.27,5.143) 4(3.81,5.144)
  rect 1.016x1.905 smd mask+0.102: 1(-3.81,-5.144)
  rect 1.1x2 smd mask+0.102: 2(-1.27,-5.143) 3(1.27,-5.143) 4(3.81,-5.143)
  silkscreen extent -5.08,-3.81 5.08,3.81
SSOP28 [mm]
  rect 0.95x0.3 smd mask+0.102: 1(-3.8,4.225) 2(-3.8,3.575) 3(-3.8,2.925) 4(-3.8,2.275) 5(-3.8,1.625) 6(-3.8,0.975) 7(-3.8,0.325) 8(-3.8,-0.325) 9(-3.8,-0.975) 10(-3.8,-1.625) 11(-3.8,-2.275) 12(-3.8,-2.925) 13(-3.8,-3.575) 14(-3.8,-4.225) 15(3.8,-4.225) 16(3.8,-3.575) 17(3.8,-2.925) 18(3.8,-2.275) 19(3.8,-1.625) 20(3.8,-0.975) 21(3.8,-0.325) 22(3.8,0.325) 23(3.8,0.975) 24(3.8,1.625) 25(3.8,2.275) 26(3.8,2.925) 27(3.8,3.575) 28(3.8,4.225)
  silkscreen extent -2.56,-4.55 2.56,4.55
ST-212-02V [mil]
  round 45 hole 45 unplated mask+4: 0(-393.7,-196.85) 0(-393.7,196.85) 0(-196.85,0) 0(0,-196.85) 0(0,196.85) 0(98.43,-196.85) 0(98.43,196.85)
  round 60 hole 30 mask+4: 1(0,-15) 1(0,0) 1(0,20) 2(-210,196.85) 2(-196.85,196.85) 2(-180,196.85) 3(-220,-196.85) 3(-196.85,-196.85) 3(-175,-196.85)
  round 60 hole 40 mask+4: 4(-393.7,98.43) 5(-393.7,0) 6(-393.7,-98.43)
  silkscreen extent -480,-248 268,248
TAN-A [mil]
  rect 50x60 smd mask+4: 1(55,0) 2(-55,0)
  silkscreen extent -95,-45 105,45
TP#1 [mil]
  round 60 hole 40 mask+4: 1(0,0.28)
  silkscreen extent -45,-45 45,45
TP#2 [mil]
  round 60 hole 40 mask+4: 1(0,0)
  silkscreen extent -45,-45 45,45
TS_PAD#1 [mm]
  rect 14x14 smd paste-15.24 mask+0.254: 1(-6.096,0)
TS_PAD#2 [mm]
  rect 14x14 smd paste-15.24 mask+0.254: 1(5.204,0)
TSOP348 [mil]
  rect 50x50 hole 30 mask+4: 1(0,0)
  round 50 hole 30 mask+4: 2(100,-1) 3(200,1)
  silkscreen extent -47,-155 248,72
TSSOP8(6.4) [mm]
  rect 0.25x1 smd mask+0.102: 1(-0.975,-3.2) 2(-0.325,-3.2) 3(0.325,-3.2) 4(0.975,-3.2) 5(0.975,3.2) 6(0.325,3.2) 7(-0.325,3.2) 8(-0.975,3.2)
  silkscreen extent -1.3,-1.94 1.3,1.94
TSSOP14 [mm]
  rect 0.3x1 smd mask+0.102: 1(-1.95,-3.2) 2(-1.3,-3.2) 3(-0.65,-3.2) 4(0,-3.2) 5(0.65,-3.2) 6(1.3,-3.2) 7(1.95,-3.2) 8(1.95,3.2) 9(1.3,3.2) 10(0.65,3.2) 11(0,3.2) 12(-0.65,3.2) 13(-1.3,3.2) 14(-1.95,3.2)
  silkscreen extent -2.28,-2.26 2.49,2.22
USB-B [mil]
  round 120 hole 95 mask+4: 0(-291,-185) 0(189,-185)
  round 50 hole 30 mask+4: 1(0,0) 2(-98,0) 3(-98,-80) 4(0,-80)
  silkscreen extent -365,-591 263,57
VSSOP8 [mm]
  rect 0.5x0.25 smd mask+0.102: 1(-1.5,0.75) 2(-1.5,0.25) 3(-1.5,-0.25) 4(-1.5,-0.75) 5(1.5,-0.75) 6(1.5,-0.25) 7(1.5,0.25) 8(1.5,0.75)
  silkscreen extent -1.09,-1 1.09,1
